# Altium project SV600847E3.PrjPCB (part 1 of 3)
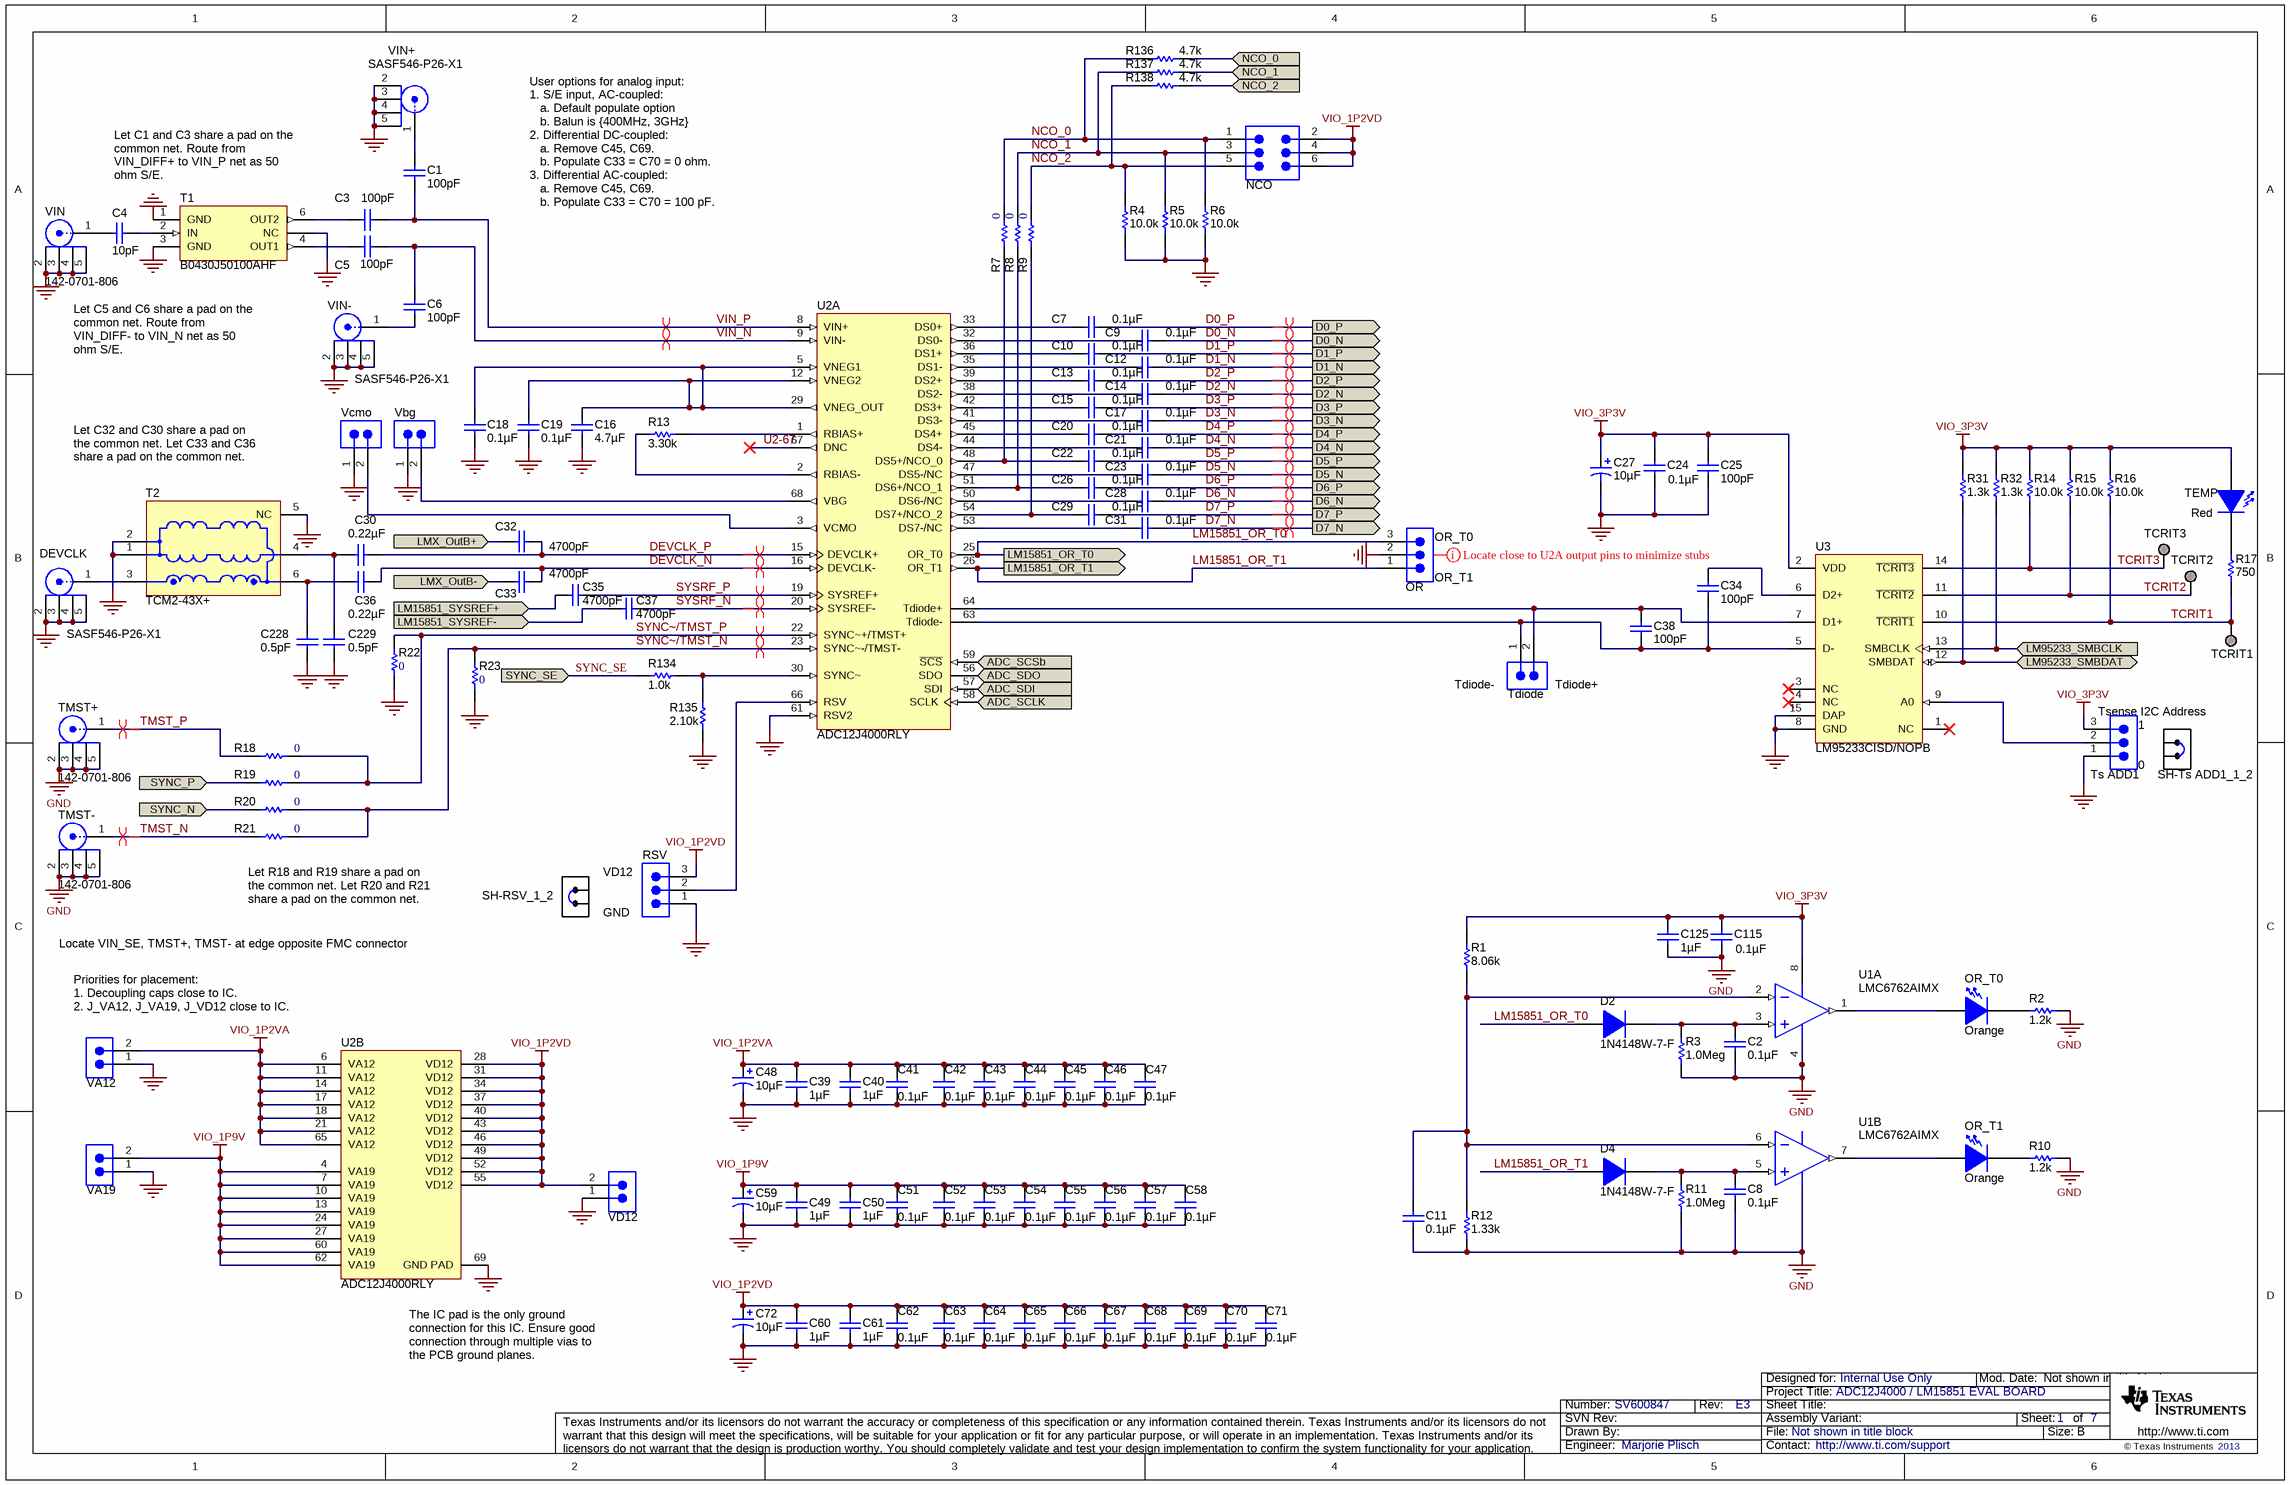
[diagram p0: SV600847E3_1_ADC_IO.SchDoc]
CopyrightYear: 2013; Drawn By: Jim Brinkhurst / Marjorie Plisch; PCB_LAYOUT: Bob Holtz; PCB_REV: E3; PRJ_Customer: Internal Use Only; PRJ_ENGINEER: Marjorie Plisch; PRJ_NUMBER: SV600847; PRJ_Title: ADC12J4000 / LM15851 EVAL BOARD; SCH_Rev: E3; TechSupport: http://www.ti.com/support
7 sheets, 522 parts. Net scope: global (net labels, ports and power ports of the same name join across sheets).
Board file: SV600847E3.PcbDoc
Sheets:
  SV600847E3_1_ADC_IO.SchDoc
  SV600847E3_2_FMC.SchDoc
  SV600847E3_3_LMX2581.SchDoc
  SV600847E3_4_LMK04828.SchDoc
  SV600847E3_5_Power.SchDoc
  SV600847E3_6_InterfaceControl.SchDoc
  SV600847E3_7_Hardware.SchDoc

## Sheet SV600847E3_1_ADC_IO.SchDoc
size 431 x 279 mm; Date: Not shown in title block; ApprovedBy: Not shown in title block; CheckedBy: Not shown in title block; Author: Not shown in title block; CompanyName: Not shown in title block; Engineer: Not shown in title block; Organization: Not shown in title block; Address1: Not shown in title block; Address2: Not shown in title block; Address3: Not shown in title block; Address4: Not shown in title block; DocumentNumber: 1; Revision: Use project parameter SCH_Rev; SheetNumber: 1; SheetTotal: 7; PageSetup: Record=PageOptions|CenterHorizontal=True|CenterVertical=True|PrintScale=0.64|XCorrection=1.00|YCorrection=1.00|PrintKind=0|BorderSize=5000000|LeftOffset=0|BottomOffset=0|Orientation=2|PaperLength=1000|PaperWidth=1000|Scale=100|PaperSource=15|PrintQuality=600|MediaType=1|DitherType=10|PaperKind=Letter|PrintScaleMode=1

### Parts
C1  ValueDisplayed: 100pF  [0201L]  (hidden comment: GRM033R71C101KA01D)
C2  ValueDisplayed: 0.1µF  [0402L]  (hidden comment: GRM155R71A104KA01D)
C3  ValueDisplayed: 100pF  [0201]  (hidden comment: GRM033R71C101KA01D)
C4  ValueDisplayed: 10pF  [0402L]  (hidden comment: GRM1555C1H100JA01D)
C5  ValueDisplayed: 100pF  [0201]  (hidden comment: GRM033R71C101KA01D)
C6  ValueDisplayed: 100pF  [0201L]  (hidden comment: GRM033R71C101KA01D)
C7  ValueDisplayed: 0.1µF  [0201]  (hidden comment: C0603X5R0J104K)
C8  ValueDisplayed: 0.1µF  [0402L]  (hidden comment: GRM155R71A104KA01D)
C9  ValueDisplayed: 0.1µF  [0201]  (hidden comment: C0603X5R0J104K)
C10  ValueDisplayed: 0.1µF  [0201]  (hidden comment: C0603X5R0J104K)
C11  ValueDisplayed: 0.1µF  [0402L]  (hidden comment: GRM155R71A104KA01D)
C12  ValueDisplayed: 0.1µF  [0201]  (hidden comment: C0603X5R0J104K)
C13  ValueDisplayed: 0.1µF  [0201]  (hidden comment: C0603X5R0J104K)
C14  ValueDisplayed: 0.1µF  [0201]  (hidden comment: C0603X5R0J104K)
C15  ValueDisplayed: 0.1µF  [0201]  (hidden comment: C0603X5R0J104K)
C16  ValueDisplayed: 4.7µF  [0402L]  (hidden comment: C1005X5R0J475M050BC)
C17  ValueDisplayed: 0.1µF  [0201]  (hidden comment: C0603X5R0J104K)
C18  ValueDisplayed: 0.1µF  [0402L]  (hidden comment: C1005X5R1A104K)
C19  ValueDisplayed: 0.1µF  [0402L]  (hidden comment: C1005X5R1A104K)
C20  ValueDisplayed: 0.1µF  [0201]  (hidden comment: C0603X5R0J104K)
C21  ValueDisplayed: 0.1µF  [0201]  (hidden comment: C0603X5R0J104K)
C22  ValueDisplayed: 0.1µF  [0201]  (hidden comment: C0603X5R0J104K)
C23  ValueDisplayed: 0.1µF  [0201]  (hidden comment: C0603X5R0J104K)
C24  ValueDisplayed: 0.1µF  [0603L]  (hidden comment: 0603YC104JAT2A)
C25  ValueDisplayed: 100pF  [0603L]  (hidden comment: 06035A101JAT2A)
C26  ValueDisplayed: 0.1µF  [0201]  (hidden comment: C0603X5R0J104K)
C27  ValueDisplayed: 10µF  [3528-21]  (hidden comment: 293D106X0010B2TE3)
C28  ValueDisplayed: 0.1µF  [0201]  (hidden comment: C0603X5R0J104K)
C29  ValueDisplayed: 0.1µF  [0201]  (hidden comment: C0603X5R0J104K)
C30  ValueDisplayed: 0.22µF  [0201]  (hidden comment: C0603X5R0J224M)
C31  ValueDisplayed: 0.1µF  [0201]  (hidden comment: C0603X5R0J104K)
C32  ValueDisplayed: 4700pF  [0201]  (hidden comment: GRM033R61A472KA01D)
C33  ValueDisplayed: 4700pF  [0201]  (hidden comment: GRM033R61A472KA01D)
C34  ValueDisplayed: 100pF  [0603L]  (hidden comment: 06035A101JAT2A)
C35  ValueDisplayed: 4700pF  [0201]  (hidden comment: GRM033R61A472KA01D)
C36  ValueDisplayed: 0.22µF  [0201]  (hidden comment: C0603X5R0J224M)
C37  ValueDisplayed: 4700pF  [0201]  (hidden comment: GRM033R61A472KA01D)
C38  ValueDisplayed: 100pF  [0603L]  (hidden comment: 06035A101JAT2A)
C39  ValueDisplayed: 1µF  [0603L]  (hidden comment: C1608X5R1A105K)
C40  ValueDisplayed: 1µF  [0603L]  (hidden comment: C1608X5R1A105K)
C41  ValueDisplayed: 0.1µF  [0201]  (hidden comment: C0603X5R0J104K)
C42  ValueDisplayed: 0.1µF  [0201]  (hidden comment: C0603X5R0J104K)
C43  ValueDisplayed: 0.1µF  [0201]  (hidden comment: C0603X5R0J104K)
C44  ValueDisplayed: 0.1µF  [0201]  (hidden comment: C0603X5R0J104K)
C45  ValueDisplayed: 0.1µF  [0201]  (hidden comment: C0603X5R0J104K)
C46  ValueDisplayed: 0.1µF  [0201]  (hidden comment: C0603X5R0J104K)
C47  ValueDisplayed: 0.1µF  [0201]  (hidden comment: C0603X5R0J104K)
C48  ValueDisplayed: 10µF  [3528-21]  (hidden comment: 293D106X0010B2TE3)
C49  ValueDisplayed: 1µF  [0603L]  (hidden comment: C1608X5R1A105K)
C50  ValueDisplayed: 1µF  [0603L]  (hidden comment: C1608X5R1A105K)
C51  ValueDisplayed: 0.1µF  [0201]  (hidden comment: C0603X5R0J104K)
C52  ValueDisplayed: 0.1µF  [0201]  (hidden comment: C0603X5R0J104K)
C53  ValueDisplayed: 0.1µF  [0201]  (hidden comment: C0603X5R0J104K)
C54  ValueDisplayed: 0.1µF  [0201]  (hidden comment: C0603X5R0J104K)
C55  ValueDisplayed: 0.1µF  [0201]  (hidden comment: C0603X5R0J104K)
C56  ValueDisplayed: 0.1µF  [0201]  (hidden comment: C0603X5R0J104K)
C57  ValueDisplayed: 0.1µF  [0201]  (hidden comment: C0603X5R0J104K)
C58  ValueDisplayed: 0.1µF  [0201]  (hidden comment: C0603X5R0J104K)
C59  ValueDisplayed: 10µF  [3528-21]  (hidden comment: 293D106X0010B2TE3)
C60  ValueDisplayed: 1µF  [0603L]  (hidden comment: C1608X5R1A105K)
C61  ValueDisplayed: 1µF  [0603L]  (hidden comment: C1608X5R1A105K)
C62  ValueDisplayed: 0.1µF  [0201]  (hidden comment: C0603X5R0J104K)
C63  ValueDisplayed: 0.1µF  [0201]  (hidden comment: C0603X5R0J104K)
C64  ValueDisplayed: 0.1µF  [0201]  (hidden comment: C0603X5R0J104K)
C65  ValueDisplayed: 0.1µF  [0201]  (hidden comment: C0603X5R0J104K)
C66  ValueDisplayed: 0.1µF  [0201]  (hidden comment: C0603X5R0J104K)
C67  ValueDisplayed: 0.1µF  [0201]  (hidden comment: C0603X5R0J104K)
C68  ValueDisplayed: 0.1µF  [0201]  (hidden comment: C0603X5R0J104K)
C69  ValueDisplayed: 0.1µF  [0201]  (hidden comment: C0603X5R0J104K)
C70  ValueDisplayed: 0.1µF  [0201]  (hidden comment: C0603X5R0J104K)
C71  ValueDisplayed: 0.1µF  [0201]  (hidden comment: C0603X5R0J104K)
C72  ValueDisplayed: 10µF  [3528-21]  (hidden comment: 293D106X0010B2TE3)
C115  ValueDisplayed: 0.1µF  [0603L]  (hidden comment: 0603YC104JAT2A)
C125  ValueDisplayed: 1µF  [0603L]  (hidden comment: C1608X5R1A105K)
C228  ValueDisplayed: 0.5pF  [0402L]  (hidden comment: 500R07S0R5BV4T)
C229  ValueDisplayed: 0.5pF  [0402L]  (hidden comment: 500R07S0R5BV4T)
D2  1N4148W-7-F  [SOD-123]
D4  1N4148W-7-F  [SOD-123]
DEVCLK  SASF546-P26-X1  [CONN_LTI_SASF546-P26-X1]
NCO  TSW-103-07-G-D  [TSW-103-07-G-D]  (value not drawn)
OR  TSW-103-07-G-S  [TSW-103-07-G-S]  (value not drawn)
OR_T0  value Orange  [LED_LTST-C190]  (hidden comment: LTST-C190KFKT)
OR_T1  value Orange  [LED_LTST-C190]  (hidden comment: LTST-C190KFKT)
R1  value 8.06k  [0402L]  (hidden comment: CRCW04028K06FKED)
R2  value 1.2k  [0402L]  (hidden comment: CRCW04021K20JNED)
R3  value 1.0Meg  [0402L]  (hidden comment: CRCW04021M00JNED)
R4  value 10.0k  [0603L]  (hidden comment: CRCW060310K0FKEA)
R5  value 10.0k  [0603L]  (hidden comment: CRCW060310K0FKEA)
R6  value 10.0k  [0603L]  (hidden comment: CRCW060310K0FKEA)
R7  value 0  [0201]  (hidden comment: ERJ-1GE0R00C)
R8  value 0  [0201]  (hidden comment: ERJ-1GE0R00C)
R9  value 0  [0201]  (hidden comment: ERJ-1GE0R00C)
R10  value 1.2k  [0402L]  (hidden comment: CRCW04021K20JNED)
R11  value 1.0Meg  [0402L]  (hidden comment: CRCW04021M00JNED)
R12  value 1.33k  [0402L]  (hidden comment: CRCW04021K33FKED)
R13  value 3.30k  [0603L]  (hidden comment: RG1608P-332-B-T5)
R14  value 10.0k  [0603L]  (hidden comment: CRCW060310K0FKEA)
R15  value 10.0k  [0603L]  (hidden comment: CRCW060310K0FKEA)
R16  value 10.0k  [0603L]  (hidden comment: CRCW060310K0FKEA)
R17  value 750  [0603L]  (hidden comment: RC0603JR-07750RL)
R18  value 0  [0201]  (hidden comment: ERJ-1GE0R00C)
R19  value 0  [0201]  (hidden comment: ERJ-1GE0R00C)
R20  value 0  [0201]  (hidden comment: ERJ-1GE0R00C)
R21  value 0  [0201]  (hidden comment: ERJ-1GE0R00C)
R22  value 0  [0201]  (hidden comment: ERJ-1GE0R00C)
R23  value 0  [0201]  (hidden comment: ERJ-1GE0R00C)
R31  value 1.3k  [0603L]  (hidden comment: RC0603JR-071K3L)
R32  value 1.3k  [0603L]  (hidden comment: RC0603JR-071K3L)
R134  value 1.0k  [0603L]  (hidden comment: RC0603JR-071KL)
R135  value 2.10k  [0603L]  (hidden comment: CRCW06032K10FKEA)
R136  value 4.7k  [0603L]  (hidden comment: CRCW06034K70JNEA)
R137  value 4.7k  [0603L]  (hidden comment: CRCW06034K70JNEA)
R138  value 4.7k  [0603L]  (hidden comment: CRCW06034K70JNEA)
RSV  TSW-103-07-G-S  [TSW-103-07-G-S]  (value not drawn)
SH-RSV_1_2  969102-0000-DA  [SNT-100-BK-G]  (value not drawn)
SH-Ts_ADD1_1_2  969102-0000-DA  [SNT-100-BK-G]  (value not drawn)
T1  B0430J50100AHF  [B0430J50100AHF]
T2  TCM2-43X+  [Mini-Circuits-DB1627]
TCRIT1  TESTPOINT  [TESTPOINT]  (value not drawn)  (no BOM)
TCRIT2  TESTPOINT  [TESTPOINT]  (value not drawn)  (no BOM)
TCRIT3  TESTPOINT  [TESTPOINT]  (value not drawn)  (no BOM)
Tdiode  TSW-102-07-G-S  [TSW-102-07-G-S]  (value not drawn)
TEMP  value Red  [LED_LTST-C170]  (hidden comment: LTST-C170KRKT)
TMST+  142-0701-806  [Johnson_142-0701-80x]
TMST-  142-0701-806  [Johnson_142-0701-80x]
Ts_ADD1  TSW-103-07-G-S  [TSW-103-07-G-S]  (value not drawn)
U1  LMC6762AIMX  [M08A_L]  (parts A,B of 2)
U2  ADC12J4000RLY  [RLY0068A]  (parts A,B of 2)
U3  LM95233CISD/NOPB  [SDA14B]
VA12  TSW-102-07-G-S  [TSW-102-07-G-S]  (value not drawn)
VA19  TSW-102-07-G-S  [TSW-102-07-G-S]  (value not drawn)
Vbg  TSW-102-07-G-S  [TSW-102-07-G-S]  (value not drawn)
Vcmo  TSW-102-07-G-S  [TSW-102-07-G-S]  (value not drawn)
VD12  TSW-102-07-G-S  [TSW-102-07-G-S]  (value not drawn)
VIN  142-0701-806  [Johnson_142-0701-80x]
VIN+  SASF546-P26-X1  [CONN_LTI_SASF546-P26-X1]
VIN-  SASF546-P26-X1  [CONN_LTI_SASF546-P26-X1]

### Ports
ADC_SCLK (in), ADC_SCSb (in), ADC_SDI (in), ADC_SDO (out), D0_N (out), D0_P (out), D1_N (out), D1_P (out), D2_N (out), D2_P (out), D3_N (out), D3_P (out), D4_N (out), D4_P (out), D5_N (out), D5_P (out), D6_N (out), D6_P (out), D7_N (out), D7_P (out), LM15851_OR_T0 (out), LM15851_OR_T1 (out), LM15851_SYSREF+, LM15851_SYSREF-, LM95233_SMBCLK (in), LM95233_SMBDAT (bidir), LMX_OutB+ (in), LMX_OutB- (in), NCO_0 (in), NCO_1 (in), NCO_2 (in), SYNC_N (in), SYNC_P (in), SYNC_SE (in)

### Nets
GND: C2.2 C8.2 C11.2 C16.1 C18.1 C19.1 C24.2 C25.2 C27.2(-) C39.2 C40.2 C41.1 C42.1 C43.1 C44.1 C45.1 C46.1 C47.1 C48.2(-) C49.2 C50.2 C51.1 C52.1 C53.1 C54.1 C55.1 C56.1 C57.1 C58.1 C59.2(-) C60.2 C61.2 C62.1 C63.1 C64.1 C65.1 C66.1 C67.1 C68.1 C69.1 C70.1 C71.1 C72.2(-) C115.2 C125.2 C228.2 C229.2 DEVCLK.2 DEVCLK.3 DEVCLK.4 DEVCLK.5 OR.2 R2.2 R3.1 R4.1 R5.1 R6.1 R10.2 R11.1 R12.1 R22.2 R23.2 R135.1 RSV.1 T1.1(GND) T1.3(GND) T1.5(NC) T2.1 T2.2 T2.5(NC) TMST+.2 TMST+.3 TMST+.4 TMST+.5 TMST-.2 TMST-.3 TMST-.4 TMST-.5 Ts_ADD1.1 U1.4(V-) U2.61(RSV2) U2.69(GND_PAD) U3.8(GND) U3.15(DAP) VA12.1 VA19.1 Vbg.1 Vcmo.1 VD12.1 VIN.2 VIN.3 VIN.4 VIN.5 VIN+.2 VIN+.3 VIN+.4 VIN+.5 VIN-.2 VIN-.3 VIN-.4 VIN-.5
VIO_1P2VA: C39.1 C40.1 C41.2 C42.2 C43.2 C44.2 C45.2 C46.2 C47.2 C48.1(+) U2.6(VA12) U2.11(VA12) U2.14(VA12) U2.17(VA12) U2.18(VA12) U2.21(VA12) U2.65(VA12) VA12.2
VIO_1P2VD: C60.1 C61.1 C62.2 C63.2 C64.2 C65.2 C66.2 C67.2 C68.2 C69.2 C70.2 C71.2 C72.1(+) NCO.2 NCO.4 NCO.6 RSV.3 U2.28(VD12) U2.31(VD12) U2.34(VD12) U2.37(VD12) U2.40(VD12) U2.43(VD12) U2.46(VD12) U2.49(VD12) U2.52(VD12) U2.55(VD12) VD12.2
VIO_1P9V: C49.1 C50.1 C51.2 C52.2 C53.2 C54.2 C55.2 C56.2 C57.2 C58.2 C59.1(+) U2.4(VA19) U2.7(VA19) U2.10(VA19) U2.13(VA19) U2.24(VA19) U2.27(VA19) U2.60(VA19) U2.62(VA19) VA19.2
VIO_3P3V: C24.1 C25.1 C27.1(+) C115.1 C125.1 R1.2 R14.2 R15.2 R16.2 R31.2 R32.2 TEMP.1(A) Ts_ADD1.3 U1.8(V+) U3.2(VDD)
D0_N: C9.1 ; port D0_N
D0_P: C7.1 ; port D0_P
D1_N: C12.1 ; port D1_N
D1_P: C10.1 ; port D1_P
D2_N: C14.1 ; port D2_N
D2_P: C13.1 ; port D2_P
D3_N: C17.1 ; port D3_N
D3_P: C15.1 ; port D3_P
D4_N: C21.1 ; port D4_N
D4_P: C20.1 ; port D4_P
D5_N: C23.1 ; port D5_N
D5_P: C22.1 ; port D5_P
D6_N: C28.1 ; port D6_N
D6_P: C26.1 ; port D6_P
D7_N: C31.1 ; port D7_N
D7_P: C29.1 ; port D7_P
DEVCLK_N: C33.1 C36.1 U2.16(DEVCLK-)
DEVCLK_P: C30.1 C32.1 U2.15(DEVCLK+)
LM15851_OR_T0: D2.2(A) OR.3 U2.25(OR_T0) ; port LM15851_OR_T0
LM15851_OR_T1: D4.2(A) OR.1 U2.26(OR_T1) ; port LM15851_OR_T1
LMX_OutB_N: C33.2 ; port LMX_OutB-
LMX_OutB_P: C32.2 ; port LMX_OutB+
NCO_0: NCO.1 R6.2 R7.1 R136.1
NCO_1: NCO.3 R5.2 R8.1 R137.1
NCO_2: NCO.5 R4.2 R9.1 R138.1
SYNC_N: R20.2 ; port SYNC_N
SYNC_P: R19.2 ; port SYNC_P
SYNC_SE: R134.1 ; port SYNC_SE
SYNC~/TMST_N: R20.1 R21.1 R23.1 U2.23(SYNC~-/TMST-)
SYNC~/TMST_P: R18.1 R19.1 R22.1 U2.22(SYNC~+/TMST+)
SYSREFTX_N: C37.2 ; port LM15851_SYSREF-
SYSREFTX_P: C35.2 ; port LM15851_SYSREF+
SYSRF_N: C37.1 U2.20(SYSREF-)
SYSRF_P: C35.1 U2.19(SYSREF+)
TCRIT1: R16.1 R17.1 TCRIT1.1 U3.10(~{TCRIT1})
TCRIT2: R15.1 TCRIT2.1 U3.11(~{TCRIT2})
TCRIT3: R14.1 TCRIT3.1 U3.14(~{TCRIT3})
TMST_N: R21.2 TMST-.1
TMST_P: R18.2 TMST+.1
U2-67: U2.67(DNC)
VIN_N: C5.1 C6.2 U2.9(VIN-)
VIN_P: C1.1 C3.1 U2.8(VIN+)
NetC1_2: C1.2 VIN+.1
NetC2_1: C2.1 D2.1(K) R3.2 U1.3(INA+)
NetC3_2: C3.2 T1.6(OUT2)
NetC4_1: C4.1 T1.2(IN)
NetC4_2: C4.2 VIN.1
NetC5_2: C5.2 T1.4(OUT1)
NetC6_1: C6.1 VIN-.1
NetC7_2: C7.2 U2.33(DS0+)
NetC8_1: C8.1 D4.1(K) R11.2 U1.5(INB+)
NetC9_2: C9.2 U2.32(DS0-)
NetC10_2: C10.2 U2.36(DS1+)
NetC11_1: C11.1 R1.1 R12.2 U1.2(INA-) U1.6(INB-)
NetC12_2: C12.2 U2.35(DS1-)
NetC13_2: C13.2 U2.39(DS2+)
NetC14_2: C14.2 U2.38(DS2-)
NetC15_2: C15.2 U2.42(DS3+)
NetC16_2: C16.2 C18.2 C19.2 U2.5(VNEG1) U2.12(VNEG2) U2.29(VNEG_OUT)
NetC17_2: C17.2 U2.41(DS3-)
NetC20_2: C20.2 U2.45(DS4+)
NetC21_2: C21.2 U2.44(DS4-)
NetC22_2: C22.2 R7.2 U2.48(DS5+/NCO_0)
NetC23_2: C23.2 U2.47(DS5-/NC)
NetC26_2: C26.2 R8.2 U2.51(DS6+/NCO_1)
NetC28_2: C28.2 U2.50(DS6-/NC)
NetC29_2: C29.2 R9.2 U2.54(DS7+/NCO_2)
NetC30_2: C30.2 C229.1 T2.4
NetC31_2: C31.2 U2.53(DS7-/NC)
NetC34_1: C34.1 U3.6(D2+)
NetC34_2: C34.2 C38.2 Tdiode.1 U2.63(Tdiode-) U3.5(D-)
NetC36_2: C36.2 C228.1 T2.6
NetC38_1: C38.1 Tdiode.2 U2.64(Tdiode+) U3.7(D1+)
NetDEVCLK_1: DEVCLK.1 T2.3
NetFMC_RX1_E12: R136.2 ; port NCO_0
NetFMC_RX1_E13: R137.2 ; port NCO_1
NetFMC_RX1_E36: R138.2 ; port NCO_2
NetOR_T0_1: OR_T0.1(A) U1.1(OUTA)
NetOR_T0_2: OR_T0.2(K) R2.1
NetOR_T1_1: OR_T1.1(A) U1.7(OUTB)
NetOR_T1_2: OR_T1.2(K) R10.1
NetR13_1: R13.1 U2.2(RBIAS-)
NetR13_2: R13.2 U2.1(RBIAS+)
NetR17_2: R17.2 TEMP.2(K)
NetR31_1: R31.1 U3.12(SMBDAT) ; port LM95233_SMBDAT
NetR32_1: R32.1 U3.13(SMBCLK) ; port LM95233_SMBCLK
NetR54_1: U2.59(~{SCS}) ; port ADC_SCSb
NetR55_1: U2.56(SDO) ; port ADC_SDO
NetR57_1: U2.57(SDI) ; port ADC_SDI
NetR58_1: U2.58(SCLK) ; port ADC_SCLK
NetR134_2: R134.2 R135.2 U2.30(SYNC~)
NetRSV_2: RSV.2 U2.66(RSV)
NetTs_ADD1_2: Ts_ADD1.2 U3.9(A0)
NetU2_3: U2.3(VCMO) Vcmo.2
NetU2_68: U2.68(VBG) Vbg.2

Not connected (* = marked no-connect by the designer): U3 1(NC)* 3(NC)* 4(NC)*

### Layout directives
differential pair: D0_N, D0_P, D1_N, D1_P, D2_N, D2_P, D3_N, D3_P, D4_N, D4_P, D5_N, D5_P, D6_N, D6_P, D7_N, D7_P, DEVCLK_N, DEVCLK_P, SYNC~/TMST_N, SYNC~/TMST_P, SYSRF_N, SYSRF_P, TMST_N, TMST_P, VIN_N, VIN_P
rule Undefined: (no net found under the mark)

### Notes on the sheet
- Let C1 and C3 share a pad on the common net. Route from VIN_DIFF+ to VIN_P net as 50 ohm S/E.
- User options for analog input:
  1. S/E input, AC-coupled:
  a. Default populate option
  b. Balun is {400MHz, 3GHz}
  2. Differential DC-coupled:
  a. Remove C45, C69.
  b. Populate C33 = C70 = 0 ohm.
  3. Differential AC-coupled:
  a. Remove C45, C69.
  b. Populate C33 = C70 = 100 pF.
- Let C5 and C6 share a pad on the common net. Route from VIN_DIFF- to VIN_N net as 50 ohm S/E.
- Let C32 and C30 share a pad on the common net. Let C33 and C36 share a pad on the common net.
- (near OR) OR_T0
- (near OR) OR_T1
- (near Tdiode) Tdiode-
- (near Tdiode) Tdiode+
- (near Ts_ADD1) Tsense I2C Address
- (near SH-Ts_ADD1_1_2) 1
- (near SH-Ts_ADD1_1_2) 0
- (near R21) Let R18 and R19 share a pad on the common net. Let R20 and R21 share a pad on the common net.
- VD12
- Locate VIN_SE, TMST+, TMST- at edge opposite FMC connector
- GND
- (near VA12) Priorities for placement:
  1. Decoupling caps close to IC.
  2. J_VA12, J_VA19, J_VD12 close to IC.
- (near U2) The IC pad is the only ground connection for this IC. Ensure good connection through multiple vias to the PCB ground planes.

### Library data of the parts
C1 C6 = GRM033R71C101KA01D: CAP, CERM, 100pF, 16V, +/-10%, X7R, 0201; Manufacturer: MuRata; Polarized: N; CompType: Capacitor; U/M: EA; Cap_F: 0.0000000001; Tolerance_%: 10; VDC_V: 16; TaMin_C: -55; TaMax_C: 125; Cap_Case: 0201
C2 C8 C11 = GRM155R71A104KA01D: CAP, CERM, 0.1uF, 10V, +/-10%, X7R, 0402; Manufacturer: MuRata; Polarized: N; CompType: Capacitor; U/M: EA; Cap_F: 0.0000001; Tolerance_%: 10; TaMin_C: -55; TaMax_C: 125; Cap_Case: 0402
C3 C5 = GRM033R71C101KA01D: CAP, CERM, 100pF, 16V, +/-10%, X7R, 0201; Manufacturer: MuRata; Polarized: N; CompType: Capacitor; U/M: EA; Cap_F: 0.0000000001; Tolerance_%: 10; VDC_V: 16; TaMin_C: -55; TaMax_C: 125
C4 = GRM1555C1H100JA01D: CAP, CERM, 10pF, 50V, +/-5%, C0G/NP0, 0402; Manufacturer: MuRata; Polarized: N; CompType: Capacitor; U/M: EA; Cap_F: 0.00000000001; Tolerance_%: 5; VDC_V: 50; TaMin_C: -55; TaMax_C: 125; Cap_Case: 0402
C7 C9 C10 C12-C15 C17 C20-C23 C26 C28 C29 C31 C41-C47 C51-C58 C62-C71 = Capacitor: CAP, CERM, 0.1uF, 6.3V, X5R, 10%, 0201; Manufacturer: TDK; Polarized: N; U/M: EA
C16 = C1005X5R0J475M050BC: CAP, CERM, 4.7uF, 6.3V, +/-20%, X5R, 0402; Manufacturer: TDK; Polarized: N; CompType: Capacitor; U/M: EA; Cap_F: 0.0000047; Tolerance_%: 20; Value1: Unknown; VDC_V: 6.3; TaMin_C: -55; TaMax_C: 85; Cap_Case: 0402
C18 C19 = C1005X5R1A104K: CAP, CERM, 0.1uF, 10V, +/-10%, X5R, 0402; Manufacturer: TDK; Polarized: N; CompType: Capacitor; U/M: EA; Cap_F: 0.0000001; Tolerance_%: 10; ESR_Ohm: 0.0186; Value1: 0.0186 ohm; TaMin_C: -55; TaMax_C: 85; Cap_Case: 0402
C24 C115 = 0603YC104JAT2A: CAP, CERM, 0.1uF, 16V, +/-5%, X7R, 0603; Manufacturer: AVX; Polarized: N; CompType: Capacitor; U/M: EA; Cap_F: 0.0000001; Tolerance_%: 5; ESR_Ohm: 0.039; Value1: 0.039 ohm; VDC_V: 16; TaMin_C: -55; TaMax_C: 125; Cap_Case: 0603
C25 C34 C38 = 06035A101JAT2A: CAP, CERM, 100pF, 50V, +/-5%, C0G/NP0, 0603; Manufacturer: AVX; Polarized: N; CompType: Capacitor; U/M: EA; Cap_F: 0.0000000001; Tolerance_%: 5; ESR_Ohm: 0.119; Value1: 0.119 ohm; VDC_V: 50; TaMin_C: -55; TaMax_C: 125; Cap_Case: 0603
C27 C48 C59 C72 = 293D106X0010B2TE3: CAP, TANT, 10uF, 10V, +/-20%, 2.5 ohm, 3528-21 SMD; Manufacturer: Vishay-Sprague; Polarized: Y; CompType: Capacitor; U/M: EA; Cap_F: 0.00001; Tolerance_%: 20; Value1: 2.5 ohm; VDC_V: 10; ESR_Ohm: 2.5; IRMS_A: 0.18; TaMin_C: -55; TaMax_C: 125; Cap_Case: B
C30 C36 = C0603X5R0J224M: CAP, CERM, 0.22uF, 6.3V, +/-20%, X5R, 0201; Manufacturer: TDK; Polarized: N; CompType: Capacitor; U/M: EA; Cap_F: 0.00000022; Tolerance_%: 20; Value1: Unknown; VDC_V: 6.3; TaMin_C: -55; TaMax_C: 85
C32 C33 C35 C37 = GRM033R61A472KA01D: CAP, CERM, 4700pF, 10V, +/-10%, X5R, 0201; Manufacturer: MuRata; Polarized: N; CompType: Capacitor; U/M: EA; Cap_F: 0.0000000047; Tolerance_%: 10; TaMin_C: -55; TaMax_C: 85
C39 C40 C49 C50 C60 C61 C125 = C1608X5R1A105K: CAP, CERM, 1uF, 10V, +/-10%, X5R, 0603; Manufacturer: TDK; Polarized: N; CompType: Capacitor; U/M: EA; Cap_F: 0.000001; Tolerance_%: 10; ESR_Ohm: 0.0057; Value1: 0.0057 ohm; TaMin_C: -55; TaMax_C: 85; Cap_Case: 0603
C228 C229 = GRM155R71A104KA01D: CAP CER 0.5PF 50V NP0 0402; Manufacturer: Johanson Technology Inc; Polarized: N; CompType: Capacitor; U/M: EA; VDC_V: 50; Cap_Case: 0402
D2 D4 = 1N4148W-7-F: Diode, Ultrafast, 100V, 0.15A, SOD-123; Manufacturer: Diodes Inc.; U/M: EA; Vf_V: 1.25; Io_A: 0.15; Vr_V: 100; TJmax_C: 150; Value: 1.25V
DEVCLK VIN+ VIN- = SASF546-P26-X1: Connector, SMA,Vertical, Thru hole w/SMT center pin; Manufacturer: Lighthorse Technologies; U/M: EA
NCO = TSW-103-07-G-D: Header, TH, 100mil, 3x2, Gold plated, 230 mil above insulator; Manufacturer: Samtec, Inc.; Alternate Manufacturer: Any; Alternate PartNumber: Equivalent; U/M: EA
OR RSV Ts_ADD1 = TSW-103-07-G-S: Header, TH, 100mil, 3x1, Gold plated, 230 mil above insulator; Manufacturer: Samtec, Inc.; Alternate Manufacturer: Any; Alternate PartNumber: Equivalent; U/M: EA
OR_T0 OR_T1 = LTST-C190KFKT: LED, Orange, SMD; Manufacturer: Lite-On; Vf_V: 2; Value2: 2V; Io_A: 0.02; Power_TotalModule: 0.075; Value1: 0.075W; U/M: EA
R1 = CRCW04028K06FKED: RES, 8.06k ohm, 1%, 0.063W, 0402; Manufacturer: Vishay-Dale; CompType: Resistor; Res_ohm: 8060; Value_Code: 8k06; Tolerance_%: 1; Power_W: 0.063; VDC_V: 50; TempCo: 100 ppm/C; EIA_Code: E96; U/M: EA
R2 R10 = CRCW04021K20JNED: RES, 1.2k ohm, 5%, 0.063W, 0402; Manufacturer: Vishay-Dale; CompType: Resistor; Res_ohm: 1200; Value_Code: 1k20; Tolerance_%: 5; Power_W: 0.063; VDC_V: 50; TempCo: 200 ppm/C; EIA_Code: E24; U/M: EA
R3 R11 = CRCW04021M00JNED: RES, 1.0Meg ohm, 5%, 0.063W, 0402; Manufacturer: Vishay-Dale; CompType: Resistor; Res_ohm: 1000000; Value_Code: 1M00; Tolerance_%: 5; Power_W: 0.063; VDC_V: 50; TempCo: 200 ppm/C; EIA_Code: E24; U/M: EA
R4-R6 R14-R16 = CRCW060310K0FKEA: RES, 10.0k ohm, 1%, 0.1W, 0603; Manufacturer: Vishay-Dale; CompType: Resistor; Res_ohm: 10000; Value_Code: 10k0; Tolerance_%: 1; Power_W: 0.1; VDC_V: 75; TempCo: 100 ppm/C; EIA_Code: E96; U/M: EA
R7-R9 R18-R23 = Res 0201 placeholder: RES 0.0 OHM 1/20W 0201 SMD; Manufacturer: Panasonic Electronic Components; CompType: Resistor
R12 = CRCW04021K33FKED: RES, 1.33k ohm, 1%, 0.063W, 0402; Manufacturer: Vishay-Dale; CompType: Resistor; Res_ohm: 1330; Value_Code: 1k33; Tolerance_%: 1; Power_W: 0.063; VDC_V: 50; TempCo: 100 ppm/C; EIA_Code: E96; U/M: EA
R13 = RG1608P-332-B-T5: RES, 3.30k ohm, 0.1%, 0.1W, 0603; Manufacturer: Susumu Co Ltd; CompType: Resistor; Res_ohm: 3300; Value_Code: 3k30; Tolerance_%: 0.1; VDC_V: 75; TempCo: 25 ppm/C; U/M: EA
R17 = RC0603JR-07750RL: RES, 750 ohm, 5%, 0.1W, 0603; Manufacturer: Yageo America; CompType: Resistor; Value_Code: 750R; Tolerance_%: 5; Power_W: 0.1; VDC_V: 50; TempCo: 100 ppm/C; EIA_Code: E24; U/M: EA
R31 R32 = RC0603JR-071K3L: RES, 1.3k ohm, 5%, 0.1W, 0603; Manufacturer: Yageo America; CompType: Resistor; Res_ohm: 1300; Value_Code: 1k30; Tolerance_%: 5; Power_W: 0.1; VDC_V: 50; TempCo: 100 ppm/C; EIA_Code: E24; U/M: EA
R134 = RC0603JR-071KL: RES, 1.0k ohm, 5%, 0.1W, 0603; Manufacturer: Yageo America; CompType: Resistor; Res_ohm: 1000; Value_Code: 1k00; Tolerance_%: 5; Power_W: 0.1; VDC_V: 50; TempCo: 100 ppm/C; EIA_Code: E24; U/M: EA
R135 = CRCW06032K10FKEA: RES, 2.10k ohm, 1%, 0.1W, 0603; Manufacturer: Vishay-Dale; CompType: Resistor; Res_ohm: 2100; Value_Code: 2k10; Tolerance_%: 1; Power_W: 0.1; VDC_V: 75; TempCo: 100 ppm/C; EIA_Code: E96; U/M: EA
R136-R138 = CRCW06034K70JNEA: RES, 4.7k ohm, 5%, 0.1W, 0603; Manufacturer: Vishay-Dale; CompType: Resistor; Res_ohm: 4700; Value_Code: 4k70; Tolerance_%: 5; Power_W: 0.1; VDC_V: 75; TempCo: 200 ppm/C; EIA_Code: E24; U/M: EA
SH-RSV_1_2 SH-Ts_ADD1_1_2 = 969102-0000-DA: Shunt, 100mil, Gold plated, Black; Manufacturer: 3M; Alternate Manufacturer: Any; Alternate PartNumber: Equivalent; U/M: EA; Value: 1x2; Note: You can "mate" this to a header by matching the designator.  i.e. use SH-J3 for header J3
T1 = B0430J50100AHF: Transformer, Multi-layer balun; Manufacturer: Anaren; SymbolCreator: a0799628; U/M: EA
T2 = TCM2-43X+: Transformer, RF, 50 ohm, 10 to 4000 MHz, SMT; Manufacturer: Minicircuits; SymbolCreator: a0799628; U/M: EA
TCRIT1-TCRIT3 = TESTPOINT: TEST POINT.  No entry in BOM.
Tdiode VA12 VA19 Vbg Vcmo VD12 = TSW-102-07-G-S: Header, TH, 100mil, 2x1, Gold plated, 230 mil above insulator; Manufacturer: Samtec, Inc.; U/M: EA
TEMP = LTST-C170KRKT: LED, Red, SMD; Manufacturer: Lite-On; Vf_V: 2; Value2: 2V; Io_A: 20; Value1: W; U/M: EA
TMST+ TMST- VIN = 142-0701-806: Connector, SMT, End launch SMA 50 ohm; Manufacturer: Emerson Network Power; Value: 50 Ohm; U/M: EA
U1 = LMC6762AIMX: Dual Micro-Power Rail-to-Rail Input CMOS Comparator with Push-Pull Output, 8-pin Narrow SOIC; Manufacturer: National Semiconductor; PackageTopMarking: NSZXTT*LMC67*62AIM; PowerWise: N
U2 = ADC12X3500RFLQNOPB: ADC12J4000RLY Ultra-Wideband RF Sampling Subsystem, RLY0068A; Alternate Manufacturer: None; Manufacturer: Texas Instruments; SymbolCreator: a0411947; CompType: IC; U/M: EA
U3 = LM95233CISD/NOPB: Dual Remote Diode and Local Temperature Sensor with SMBus Interface and TruTherm Technology, 14-pin LLP, Pb-Free; Manufacturer: National Semiconductor; PackageTopMarking: NS*UZXYTT*95233CI; PowerWise: Y; CompType: Temp Sensor IC

## Sheet SV600847E3_2_FMC.SchDoc
size 558 x 431 mm; Date: Not shown in title block; ApprovedBy: Not shown in title block; CheckedBy: Not shown in title block; Author: Not shown in title block; CompanyName: Not shown in title block; Engineer: Not shown in title block; Organization: Not shown in title block; Address1: Not shown in title block; Address2: Not shown in title block; Address3: Not shown in title block; Address4: Not shown in title block; DocumentNumber: 2; Revision: Use project parameter SCH_Rev; SheetNumber: 2; SheetTotal: 7; PageSetup: Record=PageOptions|CenterHorizontal=True|CenterVertical=True|PrintScale=0.62|XCorrection=1.00|YCorrection=1.00|PrintKind=0|BorderSize=5000000|LeftOffset=0|BottomOffset=0|Orientation=2|PaperLength=1000|PaperWidth=1000|Scale=100|PaperSource=15|PrintQuality=600|MediaType=1|DitherType=10|PaperKind=11x17|PrintScaleMode=1
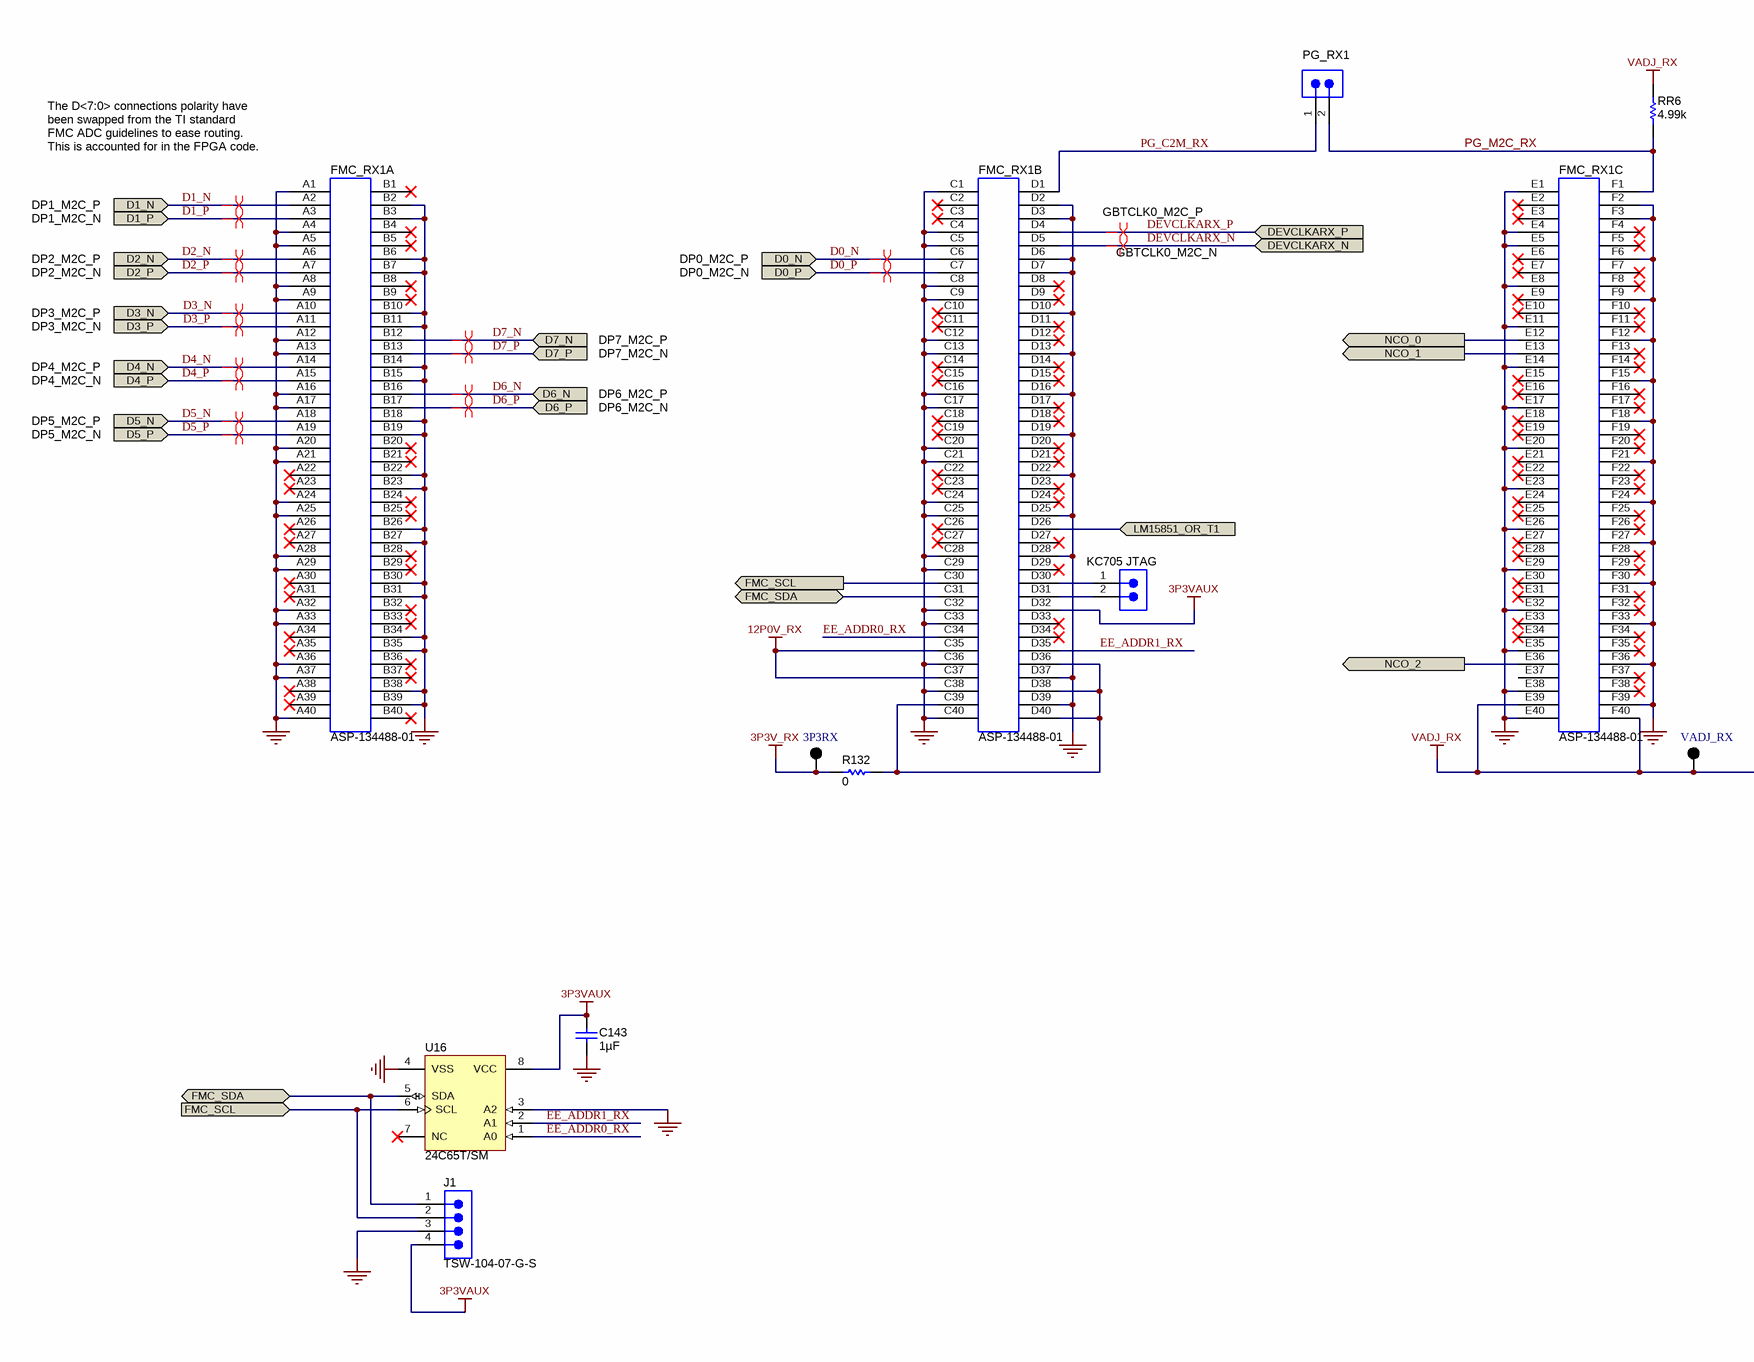
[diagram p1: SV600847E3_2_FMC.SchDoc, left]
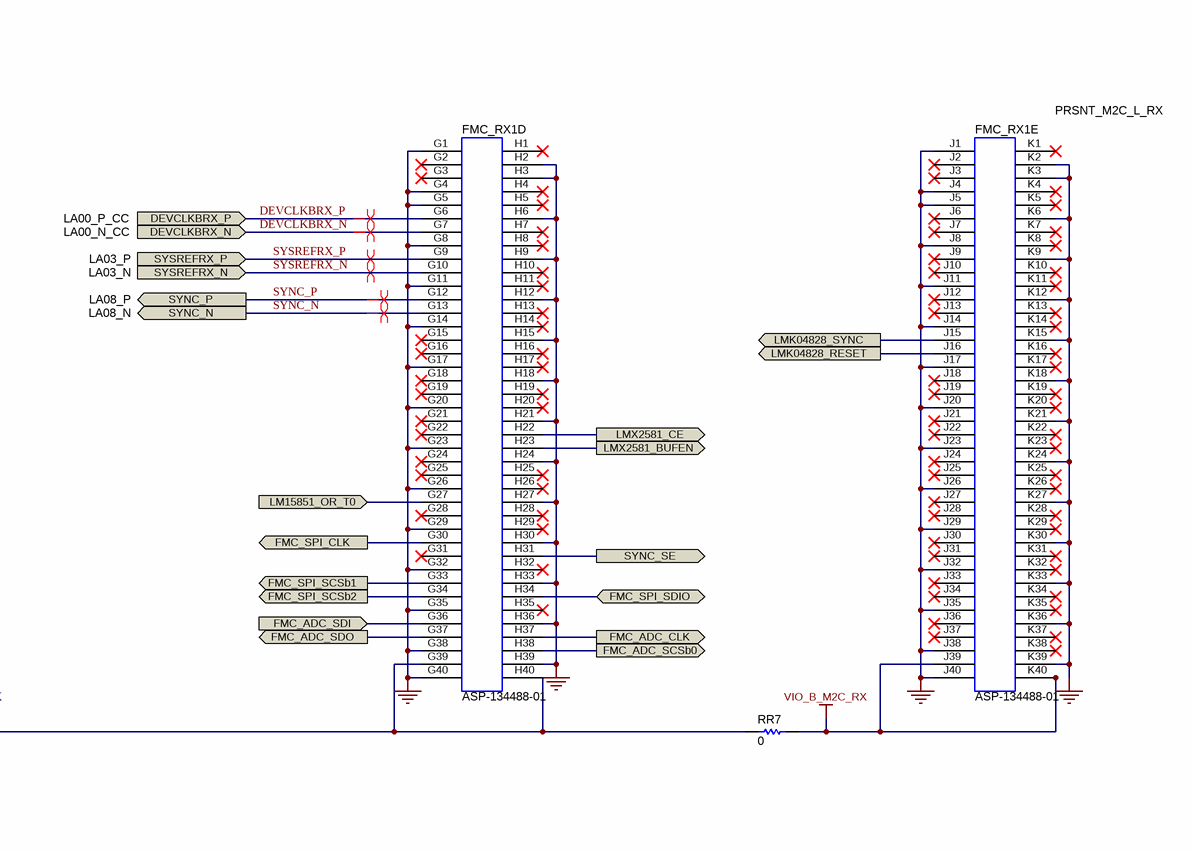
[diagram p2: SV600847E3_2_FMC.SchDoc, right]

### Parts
3P3RX  5011  [Keystone5011]  (value not drawn)
C143  ValueDisplayed: 1µF  [0603L]  (hidden comment: C1608X5R1A105K)
FMC_RX1  ASP-134488-01  [CONN_SEARAY_ASP-134488-01]  (parts A,B,C,D,E of 5)
J1  TSW-104-07-G-S  [TSW-104-07-G-S]
KC705_JTAG  TSW-102-07-G-S  [TSW-102-07-G-S]  (value not drawn)
PG_RX1  TSW-102-07-G-S  [TSW-102-07-G-S]  (value not drawn)
R132  value 0  [0603L]  (hidden comment: CRCW06030000Z0EA)
RR6  value 4.99k  [0603L]  (hidden comment: CRCW06034K99FKEA)
RR7  value 0  [0603L]  (hidden comment: ERJ-3GEY0R00V)
U16  24C65T/SM  [SOIJ-SM8_N]
VADJ_RX  5011  [Keystone5011]  (value not drawn)

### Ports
D0_N (in), D0_P (in), D1_N (in), D1_P (in), D2_N (in), D2_P (in), D3_N (in), D3_P (in), D4_N (in), D4_P (in), D5_N (in), D5_P (in), D6_N (in), D6_P (in), D7_N (in), D7_P (in), DEVCLKARX_N (in), DEVCLKARX_P (in), DEVCLKBRX_N (in), DEVCLKBRX_P (in), FMC_ADC_CLK (out), FMC_ADC_SCSb0 (out), FMC_ADC_SDI (in), FMC_ADC_SDO (out), FMC_SCL (in), FMC_SCL (out), FMC_SDA (bidir), FMC_SPI_CLK (out), FMC_SPI_SCSb1 (out), FMC_SPI_SCSb2 (out), FMC_SPI_SDIO (bidir), LM15851_OR_T0 (in), LM15851_OR_T1 (in), LMK04828_RESET (out), LMK04828_SYNC (out), LMX2581_BUFEN (out), LMX2581_CE (out), NCO_0 (out), NCO_1 (out), NCO_2 (out), SYNC_N (out), SYNC_P (out), SYNC_SE (out), SYSREFRX_N (in), SYSREFRX_P (in)

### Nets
3P3V_RX: 3P3RX.1 R132.1
3P3VAUX: C143.1 FMC_RX1.D32 J1.4 U16.8(VCC)
12P0V_RX: FMC_RX1.C35 FMC_RX1.C37
GND: C143.2 FMC_RX1.A1 FMC_RX1.A4 FMC_RX1.A5 FMC_RX1.A8 FMC_RX1.A9 FMC_RX1.A12 FMC_RX1.A13 FMC_RX1.A16 FMC_RX1.A17 FMC_RX1.A20 FMC_RX1.A21 FMC_RX1.A24 FMC_RX1.A25 FMC_RX1.A28 FMC_RX1.A29 FMC_RX1.A32 FMC_RX1.A33 FMC_RX1.A36 FMC_RX1.A37 FMC_RX1.A40 FMC_RX1.B2 FMC_RX1.B3 FMC_RX1.B6 FMC_RX1.B7 FMC_RX1.B10 FMC_RX1.B11 FMC_RX1.B14 FMC_RX1.B15 FMC_RX1.B18 FMC_RX1.B19 FMC_RX1.B22 FMC_RX1.B23 FMC_RX1.B26 FMC_RX1.B27 FMC_RX1.B30 FMC_RX1.B31 FMC_RX1.B34 FMC_RX1.B35 FMC_RX1.B38 FMC_RX1.B39 FMC_RX1.C1 FMC_RX1.C4 FMC_RX1.C5 FMC_RX1.C8 FMC_RX1.C9 FMC_RX1.C12 FMC_RX1.C13 FMC_RX1.C16 FMC_RX1.C17 FMC_RX1.C20 FMC_RX1.C21 FMC_RX1.C24 FMC_RX1.C25 FMC_RX1.C28 FMC_RX1.C29 FMC_RX1.C32 FMC_RX1.C33 FMC_RX1.C36 FMC_RX1.C38 FMC_RX1.C40 FMC_RX1.D2 FMC_RX1.D3 FMC_RX1.D6 FMC_RX1.D7 FMC_RX1.D10 FMC_RX1.D13 FMC_RX1.D16 FMC_RX1.D19 FMC_RX1.D22 FMC_RX1.D25 FMC_RX1.D28 FMC_RX1.D37 FMC_RX1.D39 FMC_RX1.E1 FMC_RX1.E4 FMC_RX1.E5 FMC_RX1.E8 FMC_RX1.E11 FMC_RX1.E14 FMC_RX1.E17 FMC_RX1.E20 FMC_RX1.E23 FMC_RX1.E26 FMC_RX1.E29 FMC_RX1.E32 FMC_RX1.E35 FMC_RX1.E38 FMC_RX1.E40 FMC_RX1.F2 FMC_RX1.F3 FMC_RX1.F6 FMC_RX1.F9 FMC_RX1.F12 FMC_RX1.F15 FMC_RX1.F18 FMC_RX1.F21 FMC_RX1.F24 FMC_RX1.F27 FMC_RX1.F30 FMC_RX1.F33 FMC_RX1.F36 FMC_RX1.F39 FMC_RX1.G1 FMC_RX1.G4 FMC_RX1.G5 FMC_RX1.G8 FMC_RX1.G11 FMC_RX1.G14 FMC_RX1.G17 FMC_RX1.G20 FMC_RX1.G23 FMC_RX1.G26 FMC_RX1.G29 FMC_RX1.G32 FMC_RX1.G35 FMC_RX1.G38 FMC_RX1.G40 FMC_RX1.H2 FMC_RX1.H3 FMC_RX1.H6 FMC_RX1.H9 FMC_RX1.H12 FMC_RX1.H15 FMC_RX1.H18 FMC_RX1.H21 FMC_RX1.H24 FMC_RX1.H27 FMC_RX1.H30 FMC_RX1.H33 FMC_RX1.H36 FMC_RX1.H39 FMC_RX1.J1 FMC_RX1.J4 FMC_RX1.J5 FMC_RX1.J8 FMC_RX1.J11 FMC_RX1.J14 FMC_RX1.J17 FMC_RX1.J20 FMC_RX1.J23 FMC_RX1.J26 FMC_RX1.J29 FMC_RX1.J32 FMC_RX1.J35 FMC_RX1.J38 FMC_RX1.J40 FMC_RX1.K2 FMC_RX1.K3 FMC_RX1.K6 FMC_RX1.K9 FMC_RX1.K12 FMC_RX1.K15 FMC_RX1.K18 FMC_RX1.K21 FMC_RX1.K24 FMC_RX1.K27 FMC_RX1.K30 FMC_RX1.K33 FMC_RX1.K36 FMC_RX1.K39 J1.3 U16.3(A2) U16.4(VSS)
VADJ_RX: FMC_RX1.E39 FMC_RX1.F40 FMC_RX1.G39 FMC_RX1.H40 RR6.2 RR7.1 VADJ_RX.1
VIO_B_M2C_RX: FMC_RX1.J39 FMC_RX1.K40 RR7.2
D0_N: FMC_RX1.C6 ; port D0_N
D0_P: FMC_RX1.C7 ; port D0_P
D1_N: FMC_RX1.A2 ; port D1_N
D1_P: FMC_RX1.A3 ; port D1_P
D2_N: FMC_RX1.A6 ; port D2_N
D2_P: FMC_RX1.A7 ; port D2_P
D3_N: FMC_RX1.A10 ; port D3_N
D3_P: FMC_RX1.A11 ; port D3_P
D4_N: FMC_RX1.A14 ; port D4_N
D4_P: FMC_RX1.A15 ; port D4_P
D5_N: FMC_RX1.A18 ; port D5_N
D5_P: FMC_RX1.A19 ; port D5_P
D6_N: FMC_RX1.B16 ; port D6_N
D6_P: FMC_RX1.B17 ; port D6_P
D7_N: FMC_RX1.B12 ; port D7_N
D7_P: FMC_RX1.B13 ; port D7_P
DEVCLKARX_N: FMC_RX1.D5 ; port DEVCLKARX_N
DEVCLKARX_P: FMC_RX1.D4 ; port DEVCLKARX_P
DEVCLKBRX_N: FMC_RX1.G7 ; port DEVCLKBRX_N
DEVCLKBRX_P: FMC_RX1.G6 ; port DEVCLKBRX_P
EE_ADDR0_RX: FMC_RX1.C34 U16.1(A0)
EE_ADDR1_RX: FMC_RX1.D35 U16.2(A1)
LM15851_OR_T0: FMC_RX1.G27 ; port LM15851_OR_T0
LM15851_OR_T1: FMC_RX1.D26 ; port LM15851_OR_T1
LMK04828_RESET: FMC_RX1.J16 ; port LMK04828_RESET
LMK04828_SYNC: FMC_RX1.J15 ; port LMK04828_SYNC
LMX2581_CE: FMC_RX1.H22 ; port LMX2581_CE
PG_C2M_RX: FMC_RX1.D1 PG_RX1.1
PG_M2C_RX: FMC_RX1.F1 PG_RX1.2 RR6.1
SYNC_N: FMC_RX1.G13 ; port SYNC_N
SYNC_P: FMC_RX1.G12 ; port SYNC_P
SYNC_SE: FMC_RX1.H31 ; port SYNC_SE
SYSREFRX_N: FMC_RX1.G10 ; port SYSREFRX_N
SYSREFRX_P: FMC_RX1.G9 ; port SYSREFRX_P
NetFMC_RX1_C30: FMC_RX1.C30 J1.2 U16.6(SCL) ; port FMC_SCL
NetFMC_RX1_C31: FMC_RX1.C31 J1.1 U16.5(SDA) ; port FMC_SDA
NetFMC_RX1_C39: FMC_RX1.C39 FMC_RX1.D36 FMC_RX1.D38 FMC_RX1.D40 R132.2
NetFMC_RX1_D30: FMC_RX1.D30 KC705_JTAG.1
NetFMC_RX1_D31: FMC_RX1.D31 KC705_JTAG.2
NetFMC_RX1_E12: FMC_RX1.E12 ; port NCO_0
NetFMC_RX1_E13: FMC_RX1.E13 ; port NCO_1
NetFMC_RX1_E36: FMC_RX1.E36 ; port NCO_2
NetFMC_RX1_G30: FMC_RX1.G30 ; port FMC_SPI_CLK
NetFMC_RX1_G33: FMC_RX1.G33 ; port FMC_SPI_SCSb1
NetFMC_RX1_G34: FMC_RX1.G34 ; port FMC_SPI_SCSb2
NetFMC_RX1_G36: FMC_RX1.G36 ; port FMC_ADC_SDI
NetFMC_RX1_G37: FMC_RX1.G37 ; port FMC_ADC_SDO
NetFMC_RX1_H23: FMC_RX1.H23 ; port LMX2581_BUFEN
NetFMC_RX1_H34: FMC_RX1.H34 ; port FMC_SPI_SDIO
NetFMC_RX1_H37: FMC_RX1.H37 ; port FMC_ADC_CLK
NetFMC_RX1_H38: FMC_RX1.H38 ; port FMC_ADC_SCSb0

Not connected (* = marked no-connect by the designer): FMC_RX1 A22* A23* A26* A27* A30* A31* A34* A35* A38* A39* B1* B4* B5* B8* B9* B20* B21* B24* B25* B28* B29* B32* B33* B36* B37* B40* C2* C3* C10* C11* C14* C15* C18* C19* C22* C23* C26* C27* D8* D9* D11* D12* D14* D15* D17* D18* D20* D21* D23* D24* D27* D29* D33* D34* E2* E3* E6* E7* E9* E10* E15* E16* E18* E19* E21* E22* E24* E25* E27* E28* E30* E31* E33* E34* E37 F4* F5* F7* F8* F10* F11* F13* F14* F16* F17* F19* F20* F22* F23* F25* F26* F28* F29* F31* F32* F34* F35* F37* F38* G2* G3* G15* G16* G18* G19* G21* G22* G24* G25* G28* G31* H1* H4* H5* H7* H8* H10* H11* H13* H14* H16* H17* H19* H20* H25* H26* H28* H29* H32* H35* J2* J3* J6* J7* J9* J10* J12* J13* J18* J19* J21* J22* J24* J25* J27* J28* J30* J31* J33* J34* J36* J37* K1* K4* K5* K7* K8* K10* K11* K13* K14* K16* K17* K19* K20* K22* K23* K25* K26* K28* K29* K31* K32* K34* K35* K37* K38*; U16 7(NC)*

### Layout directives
differential pair: D0_N, D0_P, D1_N, D1_P, D2_N, D2_P, D3_N, D3_P, D4_N, D4_P, D5_N, D5_P, D6_N, D6_P, D7_N, D7_P, DEVCLKARX_N, DEVCLKARX_P, DEVCLKBRX_N, DEVCLKBRX_P, SYNC_N, SYNC_P, SYSREFRX_N, SYSREFRX_P

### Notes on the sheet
- The D<7:0> connections polarity have been swapped from the TI standard FMC ADC guidelines to ease routing.  This is accounted for in the FPGA code.
- PRSNT_M2C_L_RX
- DP1_M2C_P
- DP1_M2C_N
- GBTCLK0_M2C_P
- DP2_M2C_P
- DP2_M2C_N
- DP0_M2C_P
- DP0_M2C_N
- GBTCLK0_M2C_N
- LA00_P_CC
- LA00_N_CC
- DP3_M2C_P
- DP3_M2C_N
- DP7_M2C_P
- DP7_M2C_N
- LA03_P
- LA03_N
- LA08_P
- LA08_N
- DP4_M2C_P
- DP4_M2C_N
- DP5_M2C_P
- DP6_M2C_P
- DP6_M2C_N
- DP5_M2C_N

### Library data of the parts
3P3RX VADJ_RX = 5011: Test Point, TH, Multipurpose, Black; Manufacturer: Keystone Electronics; CompType: Test Point Loop
C143 = C1608X5R1A105K: as C39 on sheet SV600847E3_1_ADC_IO
FMC_RX1 = ASP-134488-01: Connector, Receptacle, 400-Pos (40x10), 50x50-mil Pitch, SMT; Manufacturer: Molex; Alternate PartNumber: 45970-4315; SymbolCreator: a0799721; U/M: EA
J1 = TSW-104-07-G-S: Header, TH, 100mil, 4x1, Gold plated, 230 mil above insulator; Manufacturer: Samtec, Inc.; SymbolCreator: a0412235; U/M: EA
KC705_JTAG PG_RX1 = TSW-102-07-G-S: as Tdiode on sheet SV600847E3_1_ADC_IO
R132 = CRCW06030000Z0EA: RES, 0 ohm, 5%, 0.1W, 0603; Manufacturer: Vishay-Dale; Alternate Manufacturer: Any; Alternate PartNumber: Equivalent; CompType: Resistor; Value_Code: 0000; Tolerance_%: 5; Power_W: 0.1; VDC_V: 75; TempCo: 200 ppm/C; EIA_Code: E24; U/M: EA
RR6 = CRCW06034K99FKEA: RES, 4.99k ohm, 1%, 0.1W, 0603; Manufacturer: Vishay-Dale; CompType: Resistor; Res_ohm: 4990; Value_Code: 4k99; Tolerance_%: 1; Power_W: 0.1; VDC_V: 75; TempCo: 100 ppm/C; EIA_Code: E96; U/M: EA
RR7 = ERJ-3GEY0R00V: RES, 0 ohm, 5%, 0.1W, 0603; Manufacturer: Panasonic; CompType: Resistor; Value_Code: 0000; Tolerance_%: 5; Power_W: 0.1; VDC_V: 50; TempCo: 600 ppm/C; EIA_Code: E24; U/M: EA
U16 = 24C65T/SM: 64Kbit, 400kHz, 4.5V, I2C Serial EEPROM, 8-Pin SOIC 208mil, Commercial Temperature, Tape and Reel

## Sheet SV600847E3_3_LMX2581.SchDoc: LMX2581
size B; Date: Not shown in title block; ApprovedBy: Not shown in title block; CheckedBy: Not shown in title block; Author: Not shown in title block; CompanyName: Not shown in title block; DrawnBy: Not shown in title block; Engineer: Not shown in title block; Organization: Not shown in title block; Address1: Not shown in title block; Address2: Not shown in title block; Address3: Not shown in title block; Address4: Not shown in title block; DocumentNumber: 3; Revision: Use project parameter SCH_Rev; SheetNumber: 3; SheetTotal: 7; PageSetup: Record=PageOptions|CenterHorizontal=True|CenterVertical=True|PrintScale=0.72|XCorrection=1.00|YCorrection=1.00|PrintKind=0|BorderSize=5000000|LeftOffset=0|BottomOffset=0|Orientation=2|PaperLength=1000|PaperWidth=1000|Scale=100|PaperSource=15|PrintQuality=600|MediaType=1|DitherType=10|PaperKind=11x17|PrintScaleMode=1
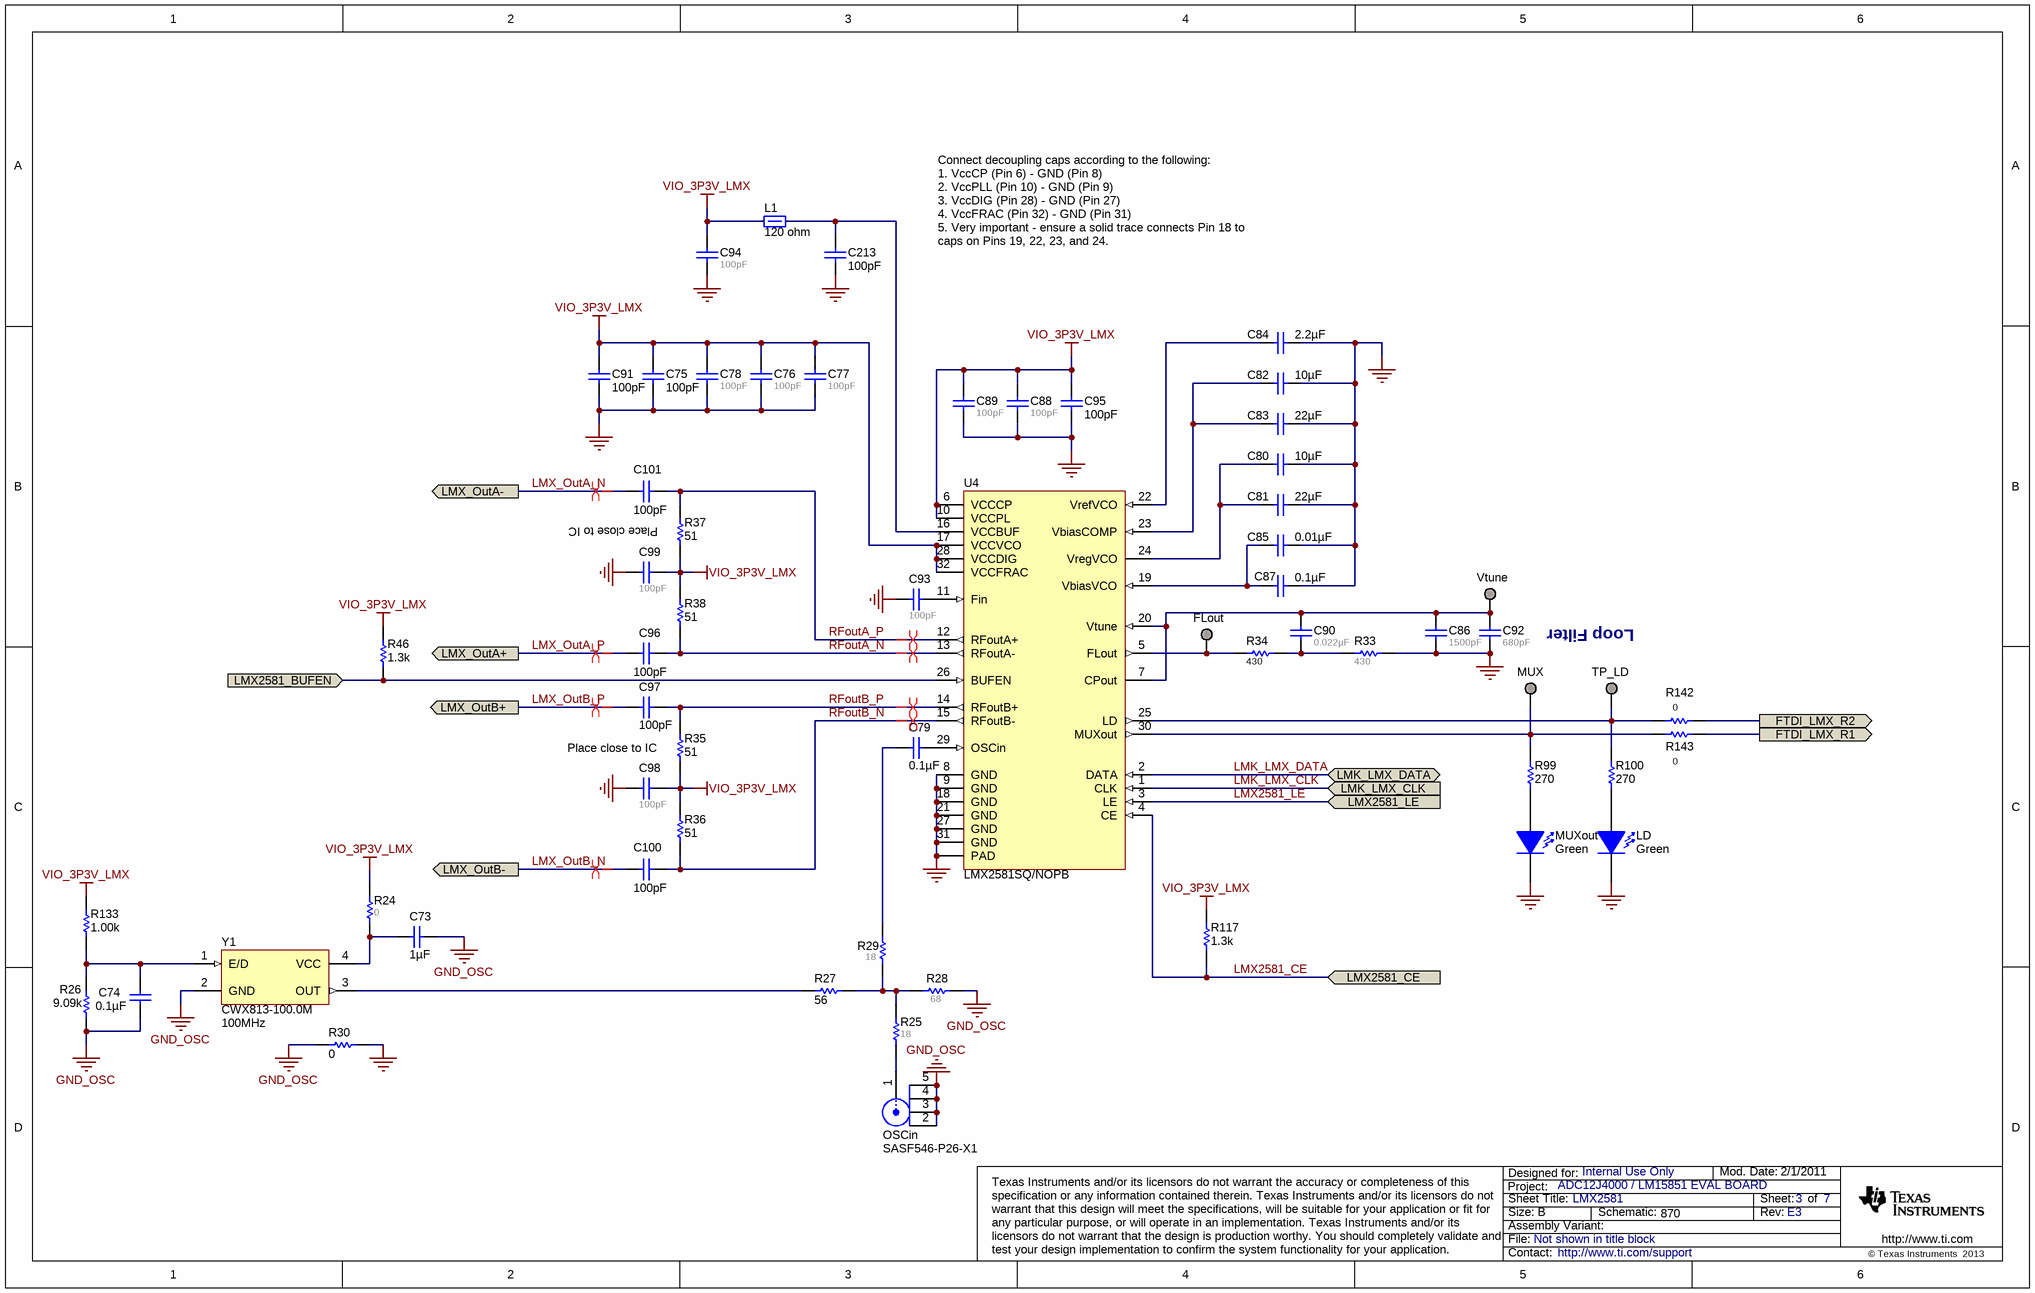
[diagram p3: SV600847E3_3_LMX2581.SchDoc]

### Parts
C73  ValueDisplayed: 1µF  [0603L]  (hidden comment: C1608X7R1C105K)
C74  ValueDisplayed: 0.1µF  [0603L]  (hidden comment: 0603YC104JAT2A)
C75  ValueDisplayed: 100pF  [0402L]  (hidden comment: GRM1555C1E101JA01D)
C76  ValueDisplayed: 100pF  [0603L]  (hidden comment: C0603C101J5GACTU)
C77  ValueDisplayed: 100pF  [0603L]  (hidden comment: C0603C101J5GACTU)
C78  ValueDisplayed: 100pF  [0603L]  (hidden comment: C0603C101J5GACTU)
C79  ValueDisplayed: 0.1µF  [0603L]  (hidden comment: 0603YC104JAT2A)
C80  ValueDisplayed: 10µF  [0603L]  (hidden comment: C1608X5R1A106M)
C81  ValueDisplayed: 22µF  [0805L]  (hidden comment: LMK212BJ226MG-T)
C82  ValueDisplayed: 10µF  [0603L]  (hidden comment: C1608X5R1A106M)
C83  ValueDisplayed: 22µF  [0805L]  (hidden comment: LMK212BJ226MG-T)
C84  ValueDisplayed: 2.2µF  [0603L]  (hidden comment: C0603C225K8PACTU)
C85  ValueDisplayed: 0.01µF  [0603L]  (hidden comment: C0603C103K1RACTU)
C86  ValueDisplayed: 1500pF  [0603L]  (hidden comment: C1608C0G1H152J)
C87  ValueDisplayed: 0.1µF  [0603L]  (hidden comment: C0603C104K5RACTU)
C88  ValueDisplayed: 100pF  [0603L]  (hidden comment: C0603C101J5GACTU)
C89  ValueDisplayed: 100pF  [0603L]  (hidden comment: C0603C101J5GACTU)
C90  ValueDisplayed: 0.022µF  [0603L]  (hidden comment: C0603C223K3RACTU)
C91  ValueDisplayed: 100pF  [0603L]  (hidden comment: C0603C101J5GACTU)
C92  ValueDisplayed: 680pF  [0603L]  (hidden comment: 06031C681JAT2A)
C93  ValueDisplayed: 100pF  [0603L]  (hidden comment: C0603C101J5GACTU)
C94  ValueDisplayed: 100pF  [0603L]  (hidden comment: C0603C101J5GACTU)
C95  ValueDisplayed: 100pF  [0402L]  (hidden comment: GRM1555C1E101JA01D)
C96  ValueDisplayed: 100pF  [0402L]  (hidden comment: GRM1555C1E101JA01D)
C97  ValueDisplayed: 100pF  [0402L]  (hidden comment: GRM1555C1E101JA01D)
C98  ValueDisplayed: 100pF  [0603L]  (hidden comment: C0603C101J5GACTU)
C99  ValueDisplayed: 100pF  [0603L]  (hidden comment: C0603C101J5GACTU)
C100  ValueDisplayed: 100pF  [0402L]  (hidden comment: GRM1555C1E101JA01D)
C101  ValueDisplayed: 100pF  [0402L]  (hidden comment: GRM1555C1E101JA01D)
C213  ValueDisplayed: 100pF  [0402L]  (hidden comment: GRM1555C1E101JA01D)
FLout  TESTPOINT  [TESTPOINT]  (value not drawn)  (no BOM)
L1  value 120 ohm  [0603]  (hidden comment: BLM18SG121TN1D)
LD  value Green  [LED_LTST-C190]  (hidden comment: LTST-C190GKT)
MUX  TESTPOINT  [TESTPOINT]  (value not drawn)  (no BOM)
MUXout  value Green  [LED_LTST-C190]  (hidden comment: LTST-C190GKT)
OSCin  SASF546-P26-X1  [CONN_LTI_SASF546-P26-X1]
R24  value 0  [0603L]  (hidden comment: CRCW06030000Z0EA)
R25  value 18  [0603L]  (hidden comment: CRCW060318R0JNEA)
R26  value 9.09k  [0603L]  (hidden comment: CRCW06039K09FKEA)
R27  value 56  [0603L]  (hidden comment: CRCW060356R0JNEA)
R28  value 68  [0603L]  (hidden comment: CRCW060368R0JNEA)
R29  value 18  [0603L]  (hidden comment: CRCW060318R0JNEA)
R30  value 0  [0603L]  (hidden comment: CRCW06030000Z0EA)
R33  value 430  [0603L]  (hidden comment: RC0603FR-07430RL)
R34  value 430  [0603L]  (hidden comment: RC0603FR-07430RL)
R35  value 51  [0402L]  (hidden comment: CRCW040251R0JNED)
R36  value 51  [0402L]  (hidden comment: CRCW040251R0JNED)
R37  value 51  [0402L]  (hidden comment: CRCW040251R0JNED)
R38  value 51  [0402L]  (hidden comment: CRCW040251R0JNED)
R46  value 1.3k  [0603L]  (hidden comment: RC0603JR-071K3L)
R99  value 270  [0603L]  (hidden comment: CRCW0603270RJNEA)
R100  value 270  [0603L]  (hidden comment: CRCW0603270RJNEA)
R117  value 1.3k  [0603L]  (hidden comment: RC0603JR-071K3L)
R133  value 1.00k  [0603L]  (hidden comment: CRCW06031K00FKEA)
R142  value 0  [0603L]  (hidden comment: CRCW06030000Z0EA)
R143  value 0  [0603L]  (hidden comment: CRCW06030000Z0EA)
TP_LD  TESTPOINT  [TESTPOINT]  (value not drawn)  (no BOM)
U4  LMX2581SQ/NOPB  [RTV0032A]
Vtune  TESTPOINT  [TESTPOINT]  (value not drawn)  (no BOM)
Y1  CWX813-100.0M  Frequency: 100MHz  [OSC_CWX]

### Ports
FTDI_LMX_R1, FTDI_LMX_R2, LMK_LMX_CLK, LMK_LMX_DATA (bidir), LMX2581_BUFEN (in), LMX2581_CE (in), LMX2581_LE, LMX_OutA+, LMX_OutA-, LMX_OutB+, LMX_OutB-

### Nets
GND: C75.1 C76.1 C77.1 C78.1 C80.1 C81.2 C82.1 C83.2 C84.1 C85.1 C86.2 C87.1 C88.2 C89.2 C91.2 C92.2 C93.2 C94.2 C95.1 C98.1 C99.1 C213.1 LD.2(K) MUXout.2(K) R30.2 R33.2 U4.8(GND) U4.9(GND) U4.18(GND) U4.21(GND) U4.27(GND) U4.31(GND) U4.33(PAD)
GND_OSC: C73.2 C74.1 OSCin.2 OSCin.3 OSCin.4 OSCin.5 R26.1 R28.1 R30.1 Y1.2(GND)
VIO_3P3V_LMX: C75.2 C76.2 C77.2 C78.2 C88.1 C89.1 C91.1 C94.1 C95.2 C98.2 C99.2 L1.1 R24.1 R35.2 R36.1 R37.2 R38.1 R46.2 R117.2 R133.2 U4.6(VCCCP) U4.10(VCCPL) U4.17(VCCVCO) U4.28(VCCDIG) U4.32(VCCFRAC)
FTDI_LMX_R1: R143.2 ; port FTDI_LMX_R1
FTDI_LMX_R2: R142.2 ; port FTDI_LMX_R2
LMK_LMX_CLK: U4.1(CLK) ; port LMK_LMX_CLK
LMK_LMX_DATA: U4.2(DATA) ; port LMK_LMX_DATA
LMX2581_CE: R117.1 U4.4(CE) ; port LMX2581_CE
LMX2581_LE: U4.3(LE) ; port LMX2581_LE
LMX_OutA_N: C101.1 ; port LMX_OutA-
LMX_OutA_P: C96.2 ; port LMX_OutA+
LMX_OutB_N: C100.1 ; port LMX_OutB-
LMX_OutB_P: C97.2 ; port LMX_OutB+
RFoutA_N: C96.1 R38.2 U4.13(RFoutA-)
RFoutA_P: C101.2 R37.1 U4.12(RFoutA+)
RFoutB_N: C100.2 R36.2 U4.15(RFoutB-)
RFoutB_P: C97.1 R35.1 U4.14(RFoutB+)
NetC73_1: C73.1 R24.2 Y1.4(VCC)
NetC74_2: C74.2 R26.2 R133.1 Y1.1(E/D)
NetC79_1: C79.1 U4.29(OSCin)
NetC79_2: C79.2 R29.2
NetC80_2: C80.2 C81.1 U4.24(VregVCO)
NetC82_2: C82.2 C83.1 U4.23(VbiasCOMP)
NetC84_2: C84.2 U4.22(VrefVCO)
NetC85_2: C85.2 C87.2 U4.19(VbiasVCO)
NetC86_1: C86.1 C90.1 C92.1 U4.7(CPout) U4.20(Vtune) Vtune.1
NetC90_2: C90.2 R33.1 R34.2
NetC93_1: C93.1 U4.11(Fin)
NetC213_2: C213.2 L1.2 U4.16(VCCBUF)
NetFLout_1: FLout.1 R34.1 U4.5(FLout)
NetFMC_RX1_H23: R46.1 U4.26(BUFEN) ; port LMX2581_BUFEN
NetLD_1: LD.1(A) R100.2
NetMUX_1: MUX.1 R99.1 R143.1 U4.30(MUXout)
NetMUXout_1: MUXout.1(A) R99.2
NetOSCin_1: OSCin.1 R25.2
NetR25_1: R25.1 R27.1 R28.2 R29.1
NetR27_2: R27.2 Y1.3(OUT)
NetR100_1: R100.1 R142.1 TP_LD.1 U4.25(LD)

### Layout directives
differential pair: LMX_OutA_N, LMX_OutA_P, LMX_OutB_N, LMX_OutB_P, RFoutA_N, RFoutA_P, RFoutB_N, RFoutB_P

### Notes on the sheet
- Connect decoupling caps according to the following:
  1. VccCP (Pin 6) - GND (Pin 8)
  2. VccPLL (Pin 10) - GND (Pin 9)
  3. VccDIG (Pin 28) - GND (Pin 27)
  4. VccFRAC (Pin 32) - GND (Pin 31)
  5. Very important - ensure a solid trace connects Pin 18 to caps on Pins 19, 22, 23, and 24.
- (near R37) Place close to IC
- Loop Filter
- (near R35) Place close to IC

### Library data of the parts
C73 = C1608X7R1C105K: CAP, CERM, 1uF, 16V, +/-10%, X7R, 0603; Manufacturer: TDK; Cap_Case: 0603; ESR_Ohm: 0.0057; Polarized: N; TaMax_C: 125; TaMin_C: -55; Tolerance_%: 10; VDC_V: 16; Cap_F: 0.000001; CompType: Capacitor; U/M: EA; Value1: 0.0057 ohm
C74 C79 = 0603YC104JAT2A: CAP, CERM, 0.1uF, 16V, +/-5%, X7R, 0603; Manufacturer: AVX; Cap_Case: 0603; ESR_Ohm: 0.039; Polarized: N; TaMax_C: 125; TaMin_C: -55; Tolerance_%: 5; VDC_V: 16; Cap_F: 0.0000001; CompType: Capacitor; Value1: 0.039 ohm; U/M: EA
C75 C95-C97 C100 C101 C213 = GRM1555C1E101JA01D: CAP, CERM, 100pF, 25V, +/-5%, C0G/NP0, 0402; Manufacturer: MuRata; Cap_Case: 0402; Polarized: N; TaMax_C: 125; TaMin_C: -55; Tolerance_%: 5; VDC_V: 25; Cap_F: 0.0000000001; CompType: Capacitor; U/M: EA
C76-C78 C88 C89 C93 C94 C98 C99 = C0603C101J5GACTU: CAP, CERM, 100pF, 50V, +/-5%, C0G/NP0, 0603; Manufacturer: Kemet; Cap_Case: 0603; Polarized: N; TaMax_C: 125; TaMin_C: -55; Tolerance_%: 5; VDC_V: 50; Cap_F: 100.0E-12; CompType: Capacitor
C80 C82 = C1608X5R1A106M: CAP, CERM, 10uF, 10V, +/-10%, C0G/NP0, 0603; Manufacturer: TDK; Cap_Case: 0603; ESR_Ohm: 0.0078; IRMS_A: 1.85; Polarized: N; TaMax_C: 85; TaMin_C: -55; Tolerance_%: 10; Cap_F: 0.00001; CompType: Capacitor; U/M: EA; Value1: 0.0078 ohm
C81 C83 = LMK212BJ226MG-T: CAP, CERM, 22uF, 10V, +/-20%, X5R, 0805; Manufacturer: Taiyo Yuden; Cap_Case: 0805; Polarized: N; TaMax_C: 85; TaMin_C: -55; Tolerance_%: 20; VDC_V: 10; Cap_F: 0.000022; CompType: Capacitor; U/M: EA
C84 = C0603C225K8PACTU: CAP, CERM, 2.2uF, 10V, +/-10%, X5R, 0603; Manufacturer: Kemet; Polarized: N; CompType: Capacitor; U/M: EA; Cap_F: 0.0000022; Tolerance_%: 10; TaMin_C: -55; TaMax_C: 85; Cap_Case: 0603
C85 = C0603C103K1RACTU: CAP, CERM, 0.01uF, 100V, +/-10%, X7R, 0603; Manufacturer: Kemet; Cap_Case: 0603; Polarized: N; TaMax_C: 125; TaMin_C: -55; Tolerance_%: 10; VDC_V: 100; Cap_F: 0.00000001; CompType: Capacitor; U/M: EA
C86 = C1608C0G1H152J: CAP, CERM, 1500pF, 50V, +/-5%, C0G/NP0, 0603; Manufacturer: TDK; Cap_Case: 0603; ESR_Ohm: 0.039; Polarized: N; TaMax_C: 125; TaMin_C: -55; Tolerance_%: 5; VDC_V: 50; Cap_F: 0.0000000015; CompType: Capacitor; Value1: 0.039 ohm; U/M: EA
C87 = C0603C104K5RACTU: CAP, CERM, 0.1uF, 50V, +/-10%, X7R, 0603; Manufacturer: Kemet; Cap_Case: 0603; Polarized: N; TaMax_C: 125; TaMin_C: -55; Tolerance_%: 10; VDC_V: 50; Cap_F: 0.0000001; CompType: Capacitor; U/M: EA
C90 = C0603C223K3RACTU: CAP, CERM, 0.022uF, 25V, +/-10%, X7R, 0603; Manufacturer: Kemet; Cap_Case: 0603; Polarized: N; TaMax_C: 125; TaMin_C: -55; Tolerance_%: 10; VDC_V: 25; Cap_F: 0.000000022; CompType: Capacitor; U/M: EA
C91 = C0603C101J5GACTU: CAP, CERM, 100pF, 50V, +/-5%, C0G/NP0, 0603; Manufacturer: Kemet; Polarized: N; CompType: Capacitor; U/M: EA; Cap_F: 0.0000000001; Tolerance_%: 5; VDC_V: 50; TaMin_C: -55; TaMax_C: 125; Cap_Case: 0603
C92 = 06031C681JAT2A: CAP, CERM, 680pF, 100V, +/-5%, X7R, 0603; Manufacturer: AVX; Cap_Case: 0603; ESR_Ohm: 0.332; Polarized: N; TaMax_C: 125; TaMin_C: -55; Tolerance_%: 5; VDC_V: 100; Cap_F: 0.00000000068; CompType: Capacitor; Value1: 0.332 ohm; U/M: EA
FLout MUX TP_LD Vtune = TESTPOINT: TEST POINT.  No entry in BOM.
L1 = BLM18SG121TN1D: 3A Ferrite Bead, 120 ohm @ 100MHz, SMD; Manufacturer: MuRata; Imax_A: 3; DCR_ohm: 0.025; Value1: 0.025 ohm; ZTyp@100MHz_Ohm: 120; U/M: EA
LD MUXout = LTST-C190GKT: LED, Green, SMD; Manufacturer: Lite-On; Vf_V: 2.1; Value2: 2.1V; Io_A: 0.02; Power_TotalModule: 0.1; Value1: 0.1W; U/M: EA
OSCin = SASF546-P26-X1: as DEVCLK on sheet SV600847E3_1_ADC_IO
R24 R142 R143 = CRCW06030000Z0EA: RES, 0 ohm, 5%, 0.1W, 0603; Manufacturer: Vishay-Dale; CompType: Resistor; Tolerance_%: 5; VDC_V: 75; Power_W: 0.1; U/M: EA; Value_Code: 0000; EIA_Code: E24
R25 R29 = CRCW060318R0JNEA: RES, 18 ohm, 5%, 0.1W, 0603; Manufacturer: Vishay-Dale; CompType: Resistor; Tolerance_%: 5; VDC_V: 75; Power_W: 0.1; U/M: EA; Value_Code: 18R0; EIA_Code: E24
R26 = CRCW06039K09FKEA: RES, 9.09k ohm, 1%, 0.1W, 0603; Manufacturer: Vishay-Dale; CompType: Resistor; Res_ohm: 9090; Value_Code: 9k09; Tolerance_%: 1; Power_W: 0.1; VDC_V: 75; TempCo: 100 ppm/C; EIA_Code: E96; U/M: EA
R27 = CRCW060356R0JNEA: RES, 56 ohm, 5%, 0.1W, 0603; Manufacturer: Vishay-Dale; CompType: Resistor; Tolerance_%: 5; VDC_V: 75; Power_W: 0.1; U/M: EA; Value_Code: 56R0; EIA_Code: E24; TempCo: 200 ppm/C
R28 = CRCW060368R0JNEA: RES, 68 ohm, 5%, 0.1W, 0603; Manufacturer: Vishay-Dale; CompType: Resistor; Tolerance_%: 5; VDC_V: 75; Power_W: 0.1; U/M: EA; Value_Code: 68R0; EIA_Code: E24
R30 = CRCW06030000Z0EA: RES, 0 ohm, 5%, 0.1W, 0603; Manufacturer: Vishay-Dale; CompType: Resistor; Value_Code: 0000; Tolerance_%: 5; Power_W: 0.1; VDC_V: 75; TempCo: 200 ppm/C; EIA_Code: E24; U/M: EA
R33 R34 = RC0603FR-07430RL: RES, 430 ohm, 1%, 0.1W, 0603; Manufacturer: Yageo America; CompType: Resistor; Tolerance_%: 1; VDC_V: 150; Power_W: 0.1; U/M: EA; Value_Code: 430R
R35-R38 = CRCW040251R0JNED: RES, 51 ohm, 5%, 0.063W, 0402; Manufacturer: Vishay-Dale; CompType: Resistor; Tolerance_%: 5; VDC_V: 50; Power_W: 0.063; U/M: EA; Value_Code: 51R0; EIA_Code: E24; TempCo_ppm/C: 200
R46 R117 = RC0603JR-071K3L: as R31 on sheet SV600847E3_1_ADC_IO
R99 R100 = CRCW0603270RJNEA: RES, 270 ohm, 5%, 0.1W, 0603; Manufacturer: Vishay-Dale; Alternate Manufacturer: Any; Alternate PartNumber: Equivalent; CompType: Resistor; Value_Code: 270R; Tolerance_%: 5; Power_W: 0.1; VDC_V: 75; TempCo: 200 ppm/C; EIA_Code: E24; U/M: EA
R133 = CRCW06031K00FKEA: RES, 1.00k ohm, 1%, 0.1W, 0603; Manufacturer: Vishay-Dale; CompType: Resistor; Tolerance_%: 1; VDC_V: 75; Power_W: 0.1; Res_ohm: 1000; TempCo_ppm/C: 100; Value_Code: 1k00; EIA_Code: E96; U/M: EA
U4 = LMX2581SQ/NOPB: LMX2581 Wideband Frequency Synthesizer with Integrated VCO, RTV0032A; Alternate Manufacturer: None; Manufacturer: Texas Instruments; SymbolCreator: a0411947; CompType: IC; U/M: EA
Y1 = CWX813-100.0M: OSC 100.0000MHZ 3.3V +-25PPM SMD; Manufacturer: Connor-Winfield; SymbolCreator: a0411947; CompType: Crystal; U/M: EA; TaMin_C: -20; TaMax_C: 70; Frequency Stability: ±25ppm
